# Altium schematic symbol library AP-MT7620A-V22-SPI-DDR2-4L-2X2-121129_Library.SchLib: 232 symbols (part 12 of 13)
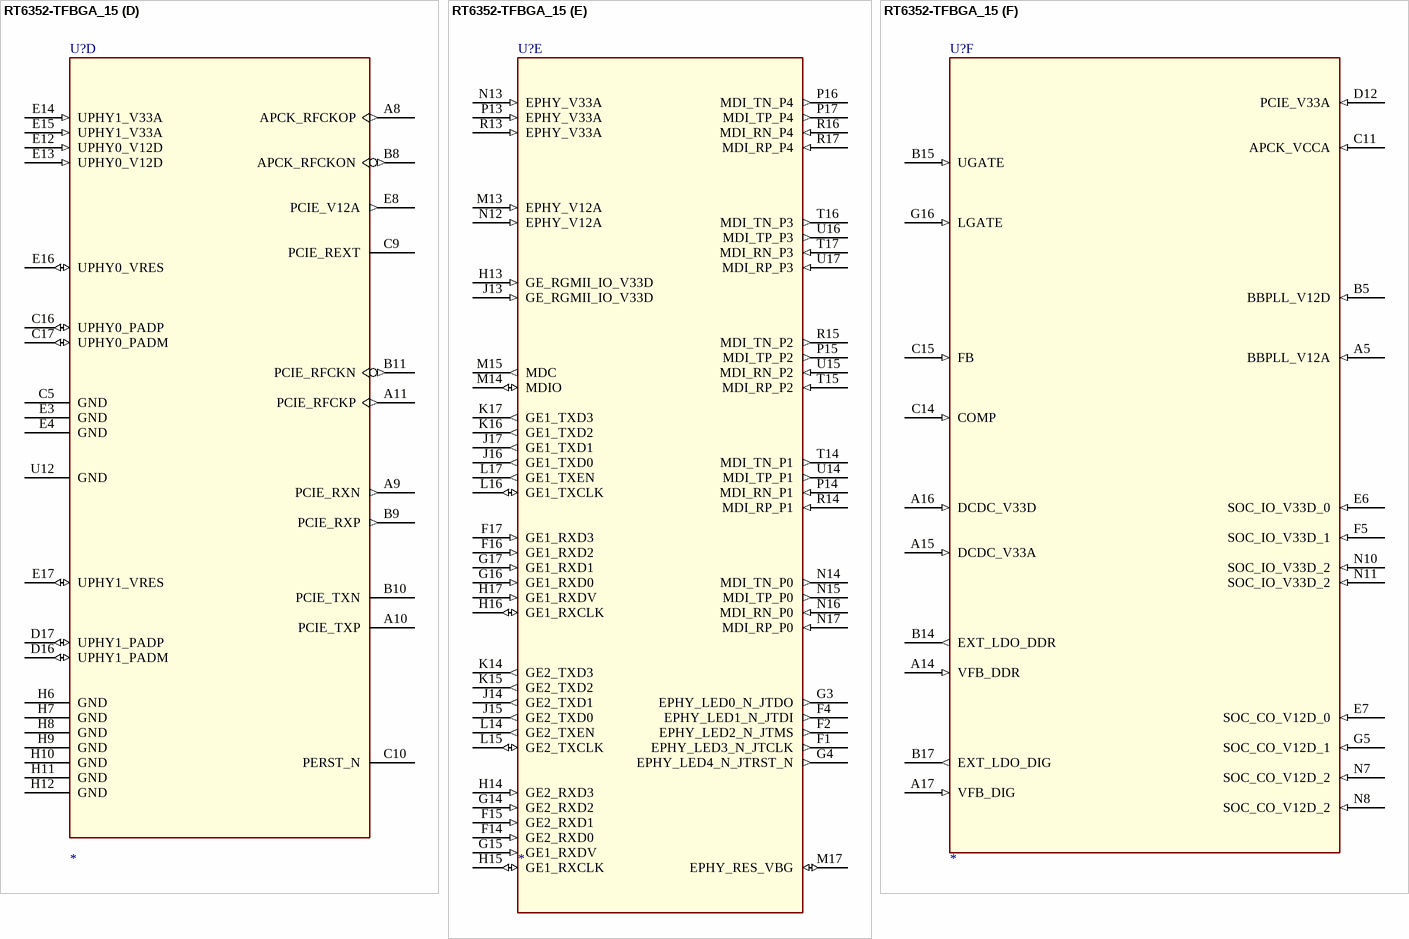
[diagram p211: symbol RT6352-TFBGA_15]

## RT6352-TFBGA_15
designator U?
footprint RT6352/BGA289/P0.65/12X12
part A pins: A1 RF0_PA2_V33P (in), A2 RF0_OUTP (out), A3 PLL_VC_CAP (out), A4 XTAL_XO (out), A6 ANT_TRN (out), B1 RF0_PA2_V33N (in), B2 RF0_OUTN (out), B3 PLL_VX_LDO, B4 XTAL_XI (out), B6 ANT_TRNB (out), C1 RF0_PA1_V33A (in), C2 RF1_VX_LDO, C3 RF0_VX_LDO, C4 XTAL_V12A (out), C6 PA_PE_G0 (out), D1 RF1_PA2_V33P (in), D2 RF1_PA2_V33N (in), D3 RF1_PA1_V33A (in), D4 BG_EXTR (out), D5 BG_V33A, D6 PA_PE_G1 (out), E1 RF1_OUTP (out), E2 RF1_OUTN (out), F3 WLED_N (out)
part B pins: F6 GND (power), F7 GND (power), F8 GND (power), F9 GND (power), F10 GND (power), F11 GND (power), F12 GND (power), G1 MD14 / MD15 (io), G2 MD9 / MD14 (io), G6 GND (power), G7 GND (power), G8 GND (power), G9 GND (power), G10 GND (power), G11 GND (power), G12 GND (power), H1 MD12 / MD13 (io), H2 MD11 / MD12 (io), H3 MRAS_N / MA5 (io), H4 MODT / MA4 (io), H5 DDR_IO_V18D/DDR_IO_V25D (in), J1 MD10 / MD11 (io), J2 MD13 / MD10 (io), J3 MCAS_N / MA7 (io), J4 MCS_N / MA6 (io), J5 DDR_IO_V18D/DDR_IO_V25D (in), K1 MD8 / MD9 (io), K2 MD15 / MD8 (io), K3 MA0 / MA8 (io), K4 MA2 / MA9 (io), K5 DDR_IOC_V12D (in), L1 MDQS1 (in), L2 MDQM1 (io), L3 MA6 / MA12 (io), L4 MA4 / MA11 (io), L5 DDR_IOC_V12D (in), M1 MCK_N (io), M2 MCK_P (io), M3 MA8 / MCKE (io), M5 MA11 / MODT (io), N1 MD5 / MD0 (io), N2 MD2 / MD1 (io), N3 MA9 / MA3 (io), N4 DDR_IO_VREF (in), N5 DDR_IO_V18D/DDR_IO_V25D (in), N6 DDR_IO_V18D/DDR_IO_V25D (in), P1 MD0 / MD2 (io), P2 MD7 / MD3 (io), P3 MA12 / MA2 (io), P4 MA7 / MA1 (io), P5 DDR_IO_VREF (in), R1 MD6 /MD4 (io), R2 MD1 / MD5 (io), R3 MA5 / MA0 (io), R4 MA3 / MA10 (io), T1 MD4 / MD6 (io), T2 MD3 / MD7 (io), T3 MA1 / MBA1 (io), T4 MBA0 / MCS_N (io), T5 MWE_N / MCAS_N (io), U1 MDQS0 (io), U2 MDQM0 (io), U3 MA10 / MBA0 (io), U4 MBA1 / MRAS_N (io), U5 MCKE / MWE_N (io)
part C pins: A7 SPI_CS0 (out), B7 SPI_CS1 (out), B17 PORST_N (in), C7 WDT_RST_N (out), C8 SPI_HOLD (out), D7 GPIO0, D8 SPI_WP (out), D9 SPI_MISO (in), D10 SPI_MOSI (out), D11 SPI_CLK (out), J6 GND (power), J7 GND (power), J8 GND (power), J9 GND (power), J10 GND (power), J11 GND (power), J12 GND (power), K6 GND (power), K7 GND (power), K8 GND (power), K9 GND (power), K10 GND (power), K11 GND (power), K12 GND (power), L6 GND (power), L7 GND (power), L8 GND (power), L9 GND (power), L10 GND (power), L11 GND (power), L12 GND (power), M6 GND (power), M7 GND (power), M8 GND (power), M9 GND (power), M10 GND (power), M11 GND (power), M12 GND (power), P6 TXD2, P7 RTS_N (out), P8 ND_D3/SD_D3 (out), P9 ND_D2/SD_D2 (out), P10 ND_D1/SD_D1 (out), P11 DSR_N (io), P12 RXD (io), R6 RXD2 (in), R7 ND_D5/bt_aux (out), R8 ND_CS_N (out), R9 ND_WP/SD_WP (out), R10 ND_D0/SD_D0 (out), R11 DCD_N (io), R12 RIN (io), T6 I2C_SD (out), T7 ND_D6/bt_wact (out), T8 ND_CLE/SD_card_detect, T9 ND_WE_N (out), T10 ND_ALE/SD_CMD (out), T11 TXD (out), T12 CTS_N (io), U6 I2C_SCLK (io), U7 ND_D7/bt_ant (out), U8 ND_D4/bt_stat (out), U9 ND_RE_N (out), U10 ND_RB_N/SD_CLK (out), U11 DTR_N (out)
part D pins: A8 APCK_RFCKOP (out), A9 PCIE_RXN (out), A10 PCIE_TXP, A11 PCIE_RFCKP (out), B8 APCK_RFCKON (out), B9 PCIE_RXP (out), B10 PCIE_TXN, B11 PCIE_RFCKN (out), C5 GND, C9 PCIE_REXT, C10 PERST_N, C16 UPHY0_PADP (io), C17 UPHY0_PADM (io), D16 UPHY1_PADM (io), D17 UPHY1_PADP (io), E3 GND, E4 GND, E8 PCIE_V12A (out), E12 UPHY0_V12D (in), E13 UPHY0_V12D (in), E14 UPHY1_V33A (in), E15 UPHY1_V33A (in), E16 UPHY0_VRES (io), E17 UPHY1_VRES (io), H6 GND (power), H7 GND (power), H8 GND (power), H9 GND (power), H10 GND (power), H11 GND (power), H12 GND (power), U12 GND
part E pins: F1 EPHY_LED3_N_JTCLK (out), F2 EPHY_LED2_N_JTMS (out), F4 EPHY_LED1_N_JTDI (out), F14 GE2_RXD0 (in), F15 GE2_RXD1 (in), F16 GE1_RXD2 (in), F17 GE1_RXD3 (in), G3 EPHY_LED0_N_JTDO (out), G4 EPHY_LED4_N_JTRST_N (out), G14 GE2_RXD2 (in), G15 GE1_RXDV (in), G16 GE1_RXD0 (in), G17 GE1_RXD1 (in), H13 GE_RGMII_IO_V33D (in), H14 GE2_RXD3 (in), H15 GE1_RXCLK (io), H16 GE1_RXCLK (io), H17 GE1_RXDV (in), J13 GE_RGMII_IO_V33D (in), J14 GE2_TXD1 (out), J15 GE2_TXD0 (out), J16 GE1_TXD0 (out), J17 GE1_TXD1 (out), K14 GE2_TXD3 (out), K15 GE2_TXD2 (out), K16 GE1_TXD2 (out), K17 GE1_TXD3 (out), L14 GE2_TXEN (out), L15 GE2_TXCLK (io), L16 GE1_TXCLK (io), L17 GE1_TXEN (out), M13 EPHY_V12A (in), M14 MDIO (io), M15 MDC (out), M17 EPHY_RES_VBG (io), N12 EPHY_V12A (in), N13 EPHY_V33A (in), N14 MDI_TN_P0 (out), N15 MDI_TP_P0 (out), N16 MDI_RN_P0 (in), N17 MDI_RP_P0 (in), P13 EPHY_V33A (in), P14 MDI_RN_P1 (in), P15 MDI_TP_P2 (out), P16 MDI_TN_P4 (out), P17 MDI_TP_P4 (out), R13 EPHY_V33A (in), R14 MDI_RP_P1 (in), R15 MDI_TN_P2 (out), R16 MDI_RN_P4 (in), R17 MDI_RP_P4 (in), T14 MDI_TN_P1 (out), T15 MDI_RP_P2 (in), T16 MDI_TN_P3 (out), T17 MDI_RN_P3 (in), U14 MDI_TP_P1 (out), U15 MDI_RN_P2 (in), U16 MDI_TP_P3 (out), U17 MDI_RP_P3 (in)
part F pins: A5 BBPLL_V12A (in), A14 VFB_DDR (in), A15 DCDC_V33A (in), A16 DCDC_V33D (in), A17 VFB_DIG (in), B5 BBPLL_V12D (in), B14 EXT_LDO_DDR (out), B15 UGATE (in), B17 EXT_LDO_DIG (out), C11 APCK_VCCA (in), C14 COMP (in), C15 FB (in), D12 PCIE_V33A (in), E6 SOC_IO_V33D_0 (in), E7 SOC_CO_V12D_0 (in), F5 SOC_IO_V33D_1 (in), G5 SOC_CO_V12D_1 (in), G16 LGATE (in), N7 SOC_CO_V12D_2 (in), N8 SOC_CO_V12D_2 (in), N10 SOC_IO_V33D_2 (in), N11 SOC_IO_V33D_2 (in)

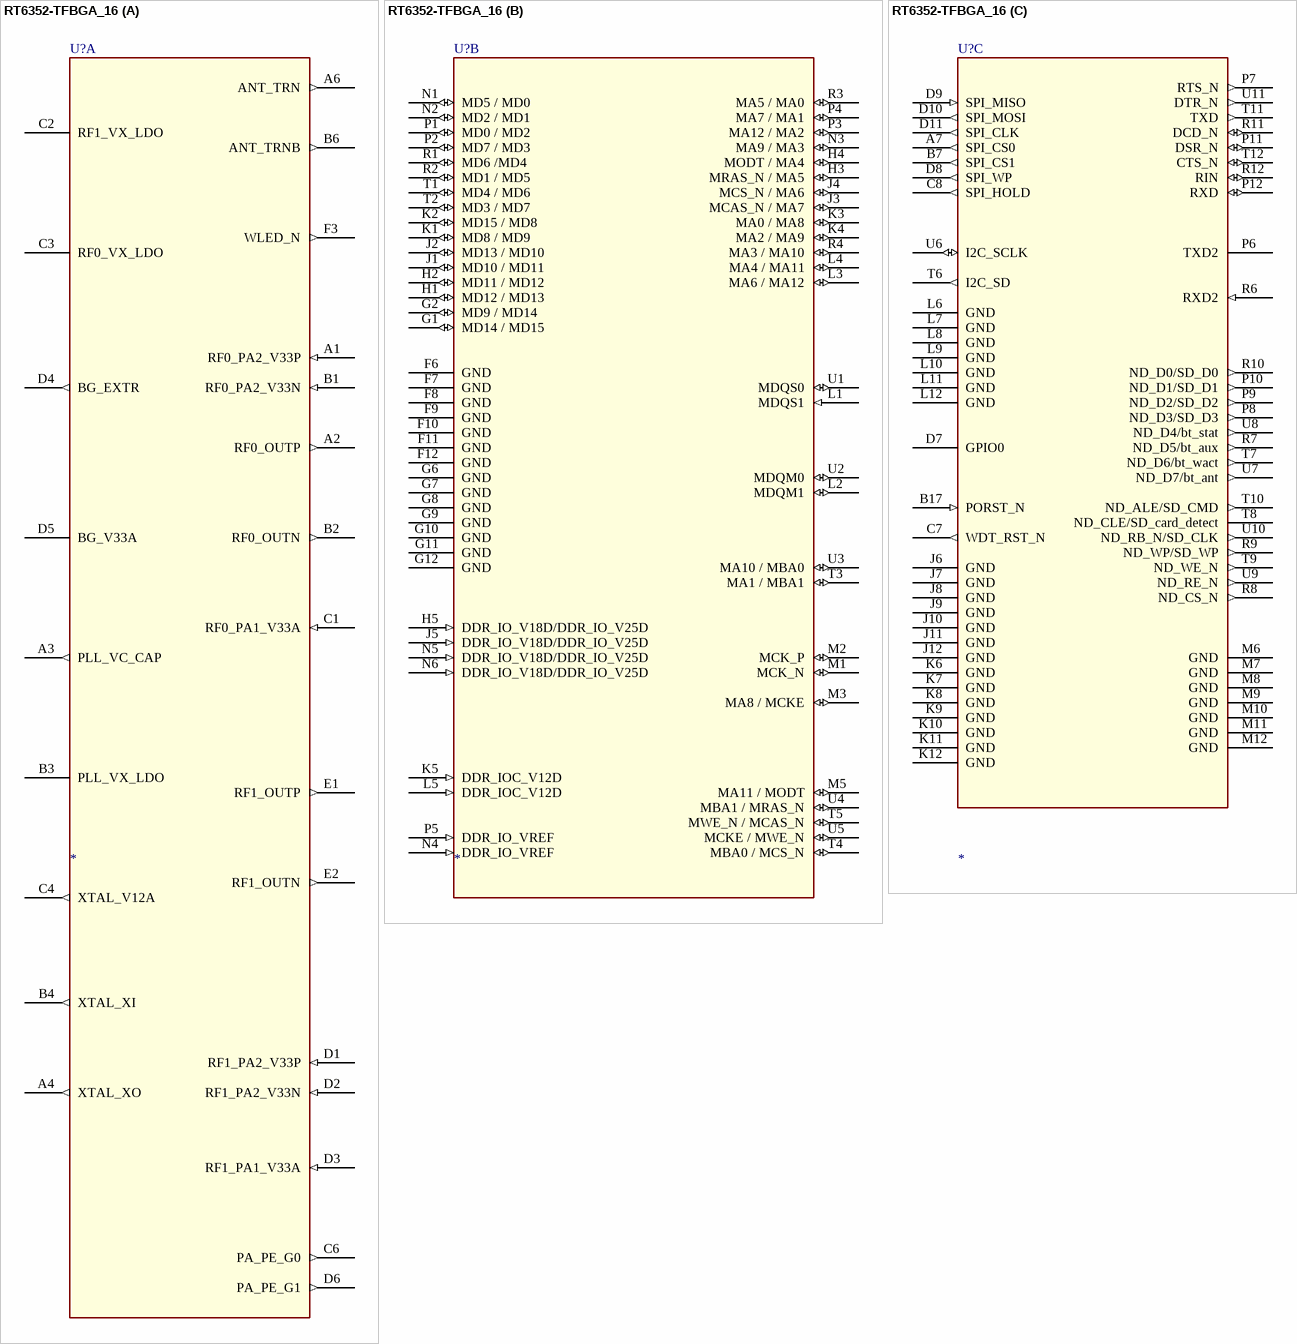
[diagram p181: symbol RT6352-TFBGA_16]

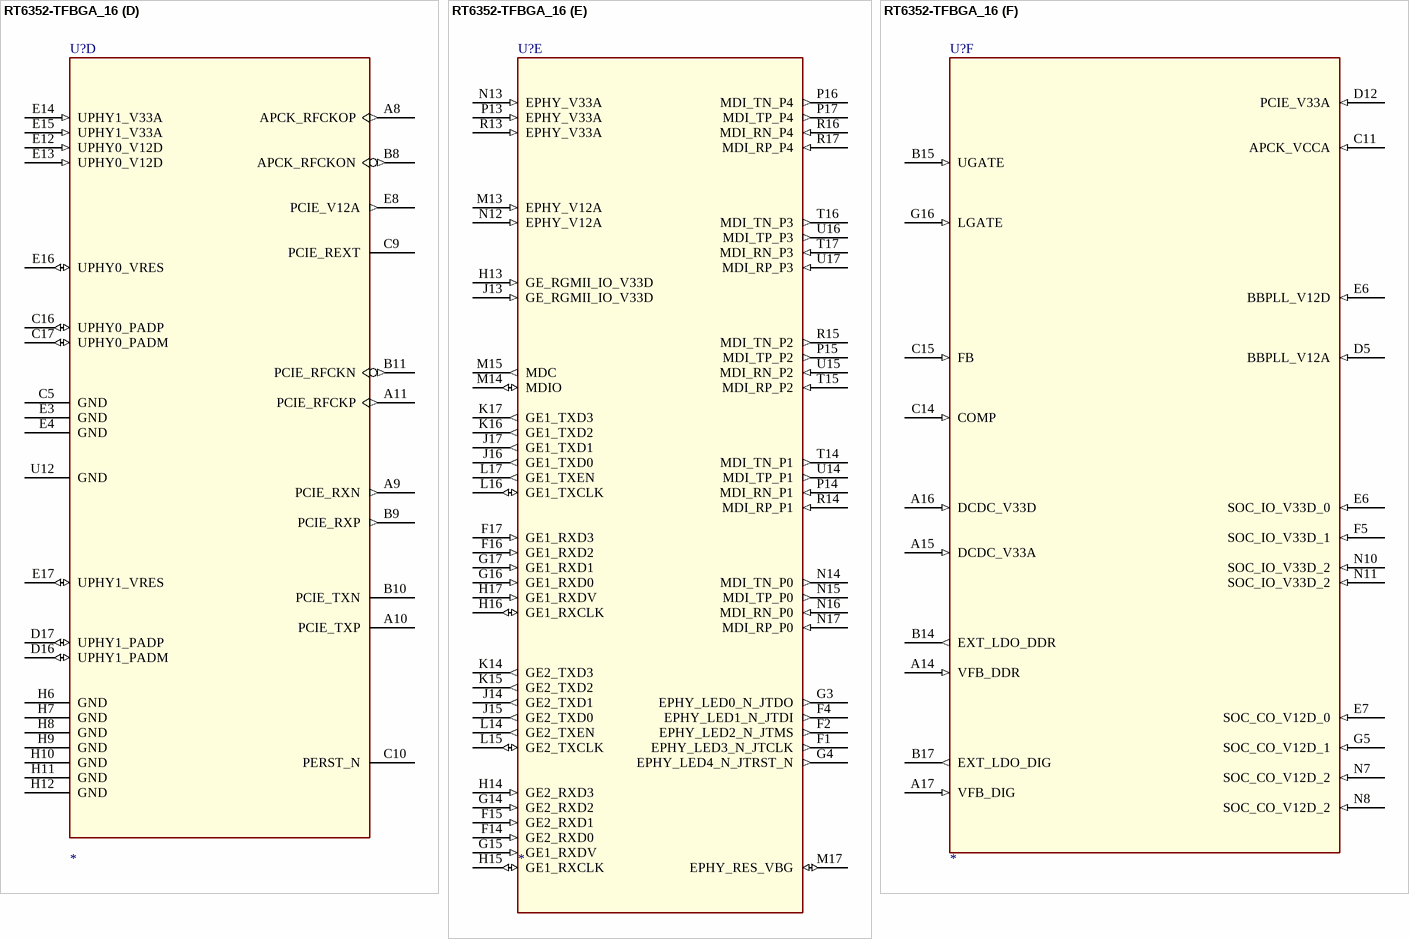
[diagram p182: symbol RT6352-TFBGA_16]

## RT6352-TFBGA_16
designator U?
footprint RT6352/BGA289/P0.65/12X12
part A pins: A1 RF0_PA2_V33P (in), A2 RF0_OUTP (out), A3 PLL_VC_CAP (out), A4 XTAL_XO (out), A6 ANT_TRN (out), B1 RF0_PA2_V33N (in), B2 RF0_OUTN (out), B3 PLL_VX_LDO, B4 XTAL_XI (out), B6 ANT_TRNB (out), C1 RF0_PA1_V33A (in), C2 RF1_VX_LDO, C3 RF0_VX_LDO, C4 XTAL_V12A (out), C6 PA_PE_G0 (out), D1 RF1_PA2_V33P (in), D2 RF1_PA2_V33N (in), D3 RF1_PA1_V33A (in), D4 BG_EXTR (out), D5 BG_V33A, D6 PA_PE_G1 (out), E1 RF1_OUTP (out), E2 RF1_OUTN (out), F3 WLED_N (out)
part B pins: F6 GND (power), F7 GND (power), F8 GND (power), F9 GND (power), F10 GND (power), F11 GND (power), F12 GND (power), G1 MD14 / MD15 (io), G2 MD9 / MD14 (io), G6 GND (power), G7 GND (power), G8 GND (power), G9 GND (power), G10 GND (power), G11 GND (power), G12 GND (power), H1 MD12 / MD13 (io), H2 MD11 / MD12 (io), H3 MRAS_N / MA5 (io), H4 MODT / MA4 (io), H5 DDR_IO_V18D/DDR_IO_V25D (in), J1 MD10 / MD11 (io), J2 MD13 / MD10 (io), J3 MCAS_N / MA7 (io), J4 MCS_N / MA6 (io), J5 DDR_IO_V18D/DDR_IO_V25D (in), K1 MD8 / MD9 (io), K2 MD15 / MD8 (io), K3 MA0 / MA8 (io), K4 MA2 / MA9 (io), K5 DDR_IOC_V12D (in), L1 MDQS1 (in), L2 MDQM1 (io), L3 MA6 / MA12 (io), L4 MA4 / MA11 (io), L5 DDR_IOC_V12D (in), M1 MCK_N (io), M2 MCK_P (io), M3 MA8 / MCKE (io), M5 MA11 / MODT (io), N1 MD5 / MD0 (io), N2 MD2 / MD1 (io), N3 MA9 / MA3 (io), N4 DDR_IO_VREF (in), N5 DDR_IO_V18D/DDR_IO_V25D (in), N6 DDR_IO_V18D/DDR_IO_V25D (in), P1 MD0 / MD2 (io), P2 MD7 / MD3 (io), P3 MA12 / MA2 (io), P4 MA7 / MA1 (io), P5 DDR_IO_VREF (in), R1 MD6 /MD4 (io), R2 MD1 / MD5 (io), R3 MA5 / MA0 (io), R4 MA3 / MA10 (io), T1 MD4 / MD6 (io), T2 MD3 / MD7 (io), T3 MA1 / MBA1 (io), T4 MBA0 / MCS_N (io), T5 MWE_N / MCAS_N (io), U1 MDQS0 (io), U2 MDQM0 (io), U3 MA10 / MBA0 (io), U4 MBA1 / MRAS_N (io), U5 MCKE / MWE_N (io)
part C pins: A7 SPI_CS0 (out), B7 SPI_CS1 (out), B17 PORST_N (in), C7 WDT_RST_N (out), C8 SPI_HOLD (out), D7 GPIO0, D8 SPI_WP (out), D9 SPI_MISO (in), D10 SPI_MOSI (out), D11 SPI_CLK (out), J6 GND (power), J7 GND (power), J8 GND (power), J9 GND (power), J10 GND (power), J11 GND (power), J12 GND (power), K6 GND (power), K7 GND (power), K8 GND (power), K9 GND (power), K10 GND (power), K11 GND (power), K12 GND (power), L6 GND (power), L7 GND (power), L8 GND (power), L9 GND (power), L10 GND (power), L11 GND (power), L12 GND (power), M6 GND (power), M7 GND (power), M8 GND (power), M9 GND (power), M10 GND (power), M11 GND (power), M12 GND (power), P6 TXD2, P7 RTS_N (out), P8 ND_D3/SD_D3 (out), P9 ND_D2/SD_D2 (out), P10 ND_D1/SD_D1 (out), P11 DSR_N (io), P12 RXD (io), R6 RXD2 (in), R7 ND_D5/bt_aux (out), R8 ND_CS_N (out), R9 ND_WP/SD_WP (out), R10 ND_D0/SD_D0 (out), R11 DCD_N (io), R12 RIN (io), T6 I2C_SD (out), T7 ND_D6/bt_wact (out), T8 ND_CLE/SD_card_detect, T9 ND_WE_N (out), T10 ND_ALE/SD_CMD (out), T11 TXD (out), T12 CTS_N (io), U6 I2C_SCLK (io), U7 ND_D7/bt_ant (out), U8 ND_D4/bt_stat (out), U9 ND_RE_N (out), U10 ND_RB_N/SD_CLK (out), U11 DTR_N (out)
part D pins: A8 APCK_RFCKOP (out), A9 PCIE_RXN (out), A10 PCIE_TXP, A11 PCIE_RFCKP (out), B8 APCK_RFCKON (out), B9 PCIE_RXP (out), B10 PCIE_TXN, B11 PCIE_RFCKN (out), C5 GND, C9 PCIE_REXT, C10 PERST_N, C16 UPHY0_PADP (io), C17 UPHY0_PADM (io), D16 UPHY1_PADM (io), D17 UPHY1_PADP (io), E3 GND, E4 GND, E8 PCIE_V12A (out), E12 UPHY0_V12D (in), E13 UPHY0_V12D (in), E14 UPHY1_V33A (in), E15 UPHY1_V33A (in), E16 UPHY0_VRES (io), E17 UPHY1_VRES (io), H6 GND (power), H7 GND (power), H8 GND (power), H9 GND (power), H10 GND (power), H11 GND (power), H12 GND (power), U12 GND
part E pins: F1 EPHY_LED3_N_JTCLK (out), F2 EPHY_LED2_N_JTMS (out), F4 EPHY_LED1_N_JTDI (out), F14 GE2_RXD0 (in), F15 GE2_RXD1 (in), F16 GE1_RXD2 (in), F17 GE1_RXD3 (in), G3 EPHY_LED0_N_JTDO (out), G4 EPHY_LED4_N_JTRST_N (out), G14 GE2_RXD2 (in), G15 GE1_RXDV (in), G16 GE1_RXD0 (in), G17 GE1_RXD1 (in), H13 GE_RGMII_IO_V33D (in), H14 GE2_RXD3 (in), H15 GE1_RXCLK (io), H16 GE1_RXCLK (io), H17 GE1_RXDV (in), J13 GE_RGMII_IO_V33D (in), J14 GE2_TXD1 (out), J15 GE2_TXD0 (out), J16 GE1_TXD0 (out), J17 GE1_TXD1 (out), K14 GE2_TXD3 (out), K15 GE2_TXD2 (out), K16 GE1_TXD2 (out), K17 GE1_TXD3 (out), L14 GE2_TXEN (out), L15 GE2_TXCLK (io), L16 GE1_TXCLK (io), L17 GE1_TXEN (out), M13 EPHY_V12A (in), M14 MDIO (io), M15 MDC (out), M17 EPHY_RES_VBG (io), N12 EPHY_V12A (in), N13 EPHY_V33A (in), N14 MDI_TN_P0 (out), N15 MDI_TP_P0 (out), N16 MDI_RN_P0 (in), N17 MDI_RP_P0 (in), P13 EPHY_V33A (in), P14 MDI_RN_P1 (in), P15 MDI_TP_P2 (out), P16 MDI_TN_P4 (out), P17 MDI_TP_P4 (out), R13 EPHY_V33A (in), R14 MDI_RP_P1 (in), R15 MDI_TN_P2 (out), R16 MDI_RN_P4 (in), R17 MDI_RP_P4 (in), T14 MDI_TN_P1 (out), T15 MDI_RP_P2 (in), T16 MDI_TN_P3 (out), T17 MDI_RN_P3 (in), U14 MDI_TP_P1 (out), U15 MDI_RN_P2 (in), U16 MDI_TP_P3 (out), U17 MDI_RP_P3 (in)
part F pins: A14 VFB_DDR (in), A15 DCDC_V33A (in), A16 DCDC_V33D (in), A17 VFB_DIG (in), B14 EXT_LDO_DDR (out), B15 UGATE (in), B17 EXT_LDO_DIG (out), C11 APCK_VCCA (in), C14 COMP (in), C15 FB (in), D5 BBPLL_V12A (in), D12 PCIE_V33A (in), E6 SOC_IO_V33D_0 (in), E6 BBPLL_V12D (in), E7 SOC_CO_V12D_0 (in), F5 SOC_IO_V33D_1 (in), G5 SOC_CO_V12D_1 (in), G16 LGATE (in), N7 SOC_CO_V12D_2 (in), N8 SOC_CO_V12D_2 (in), N10 SOC_IO_V33D_2 (in), N11 SOC_IO_V33D_2 (in)

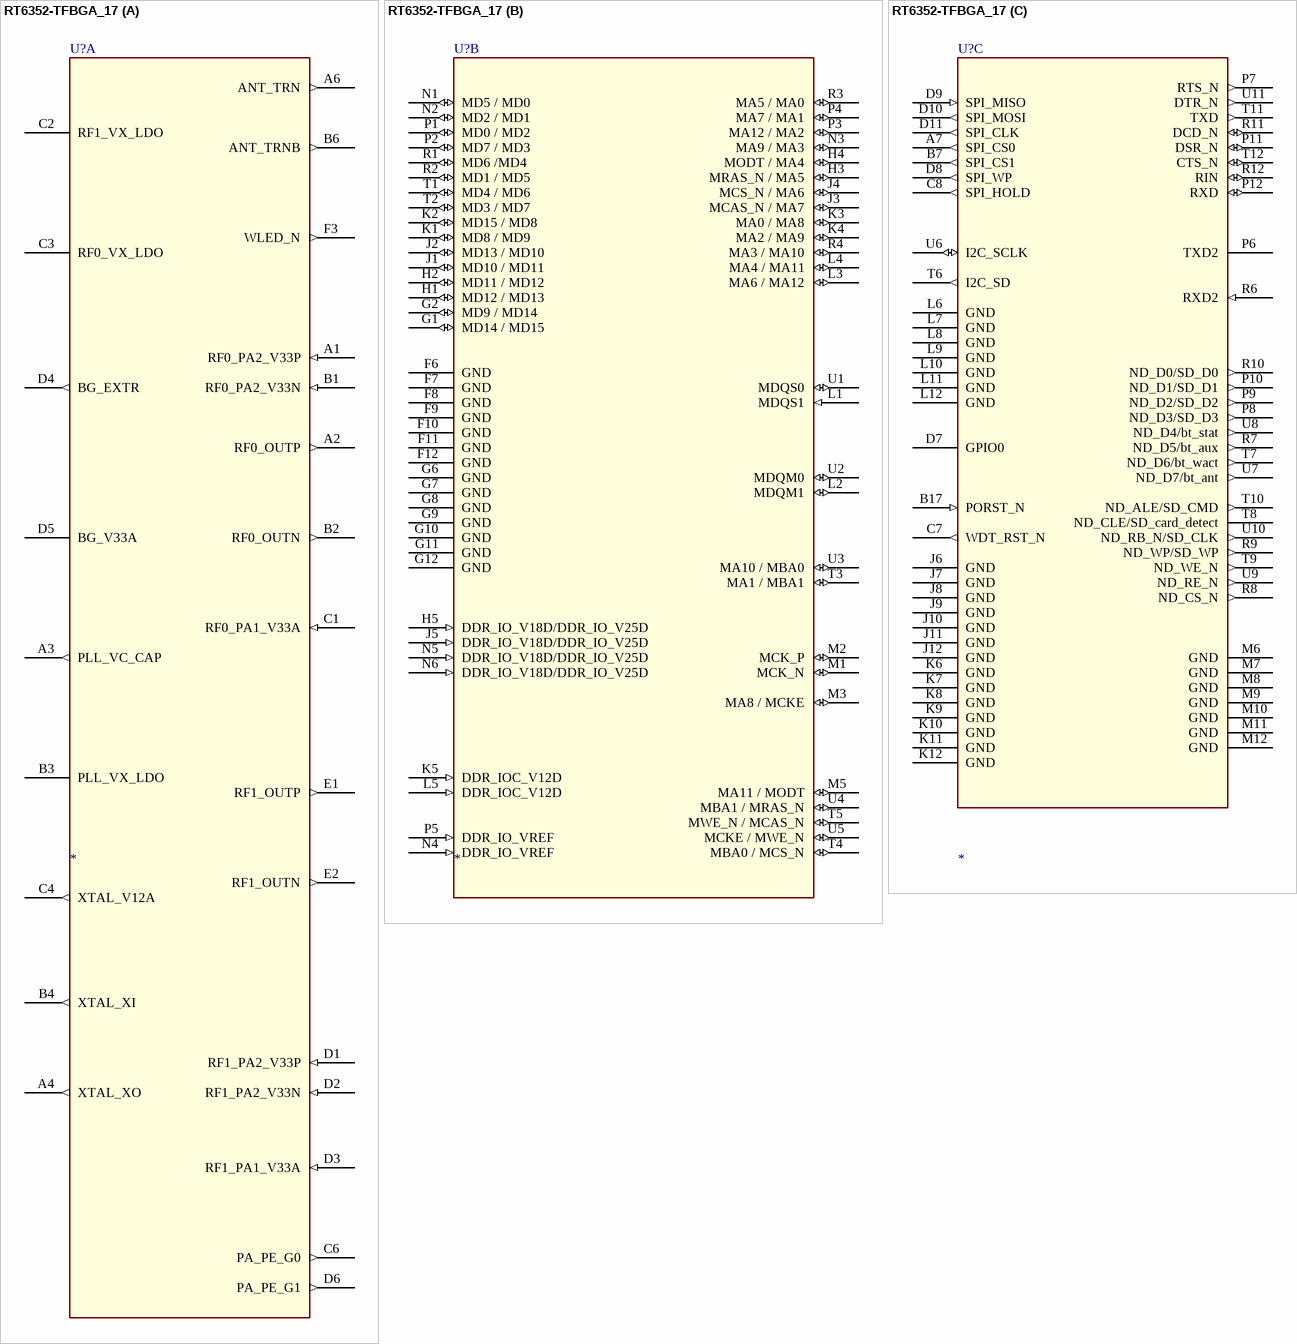
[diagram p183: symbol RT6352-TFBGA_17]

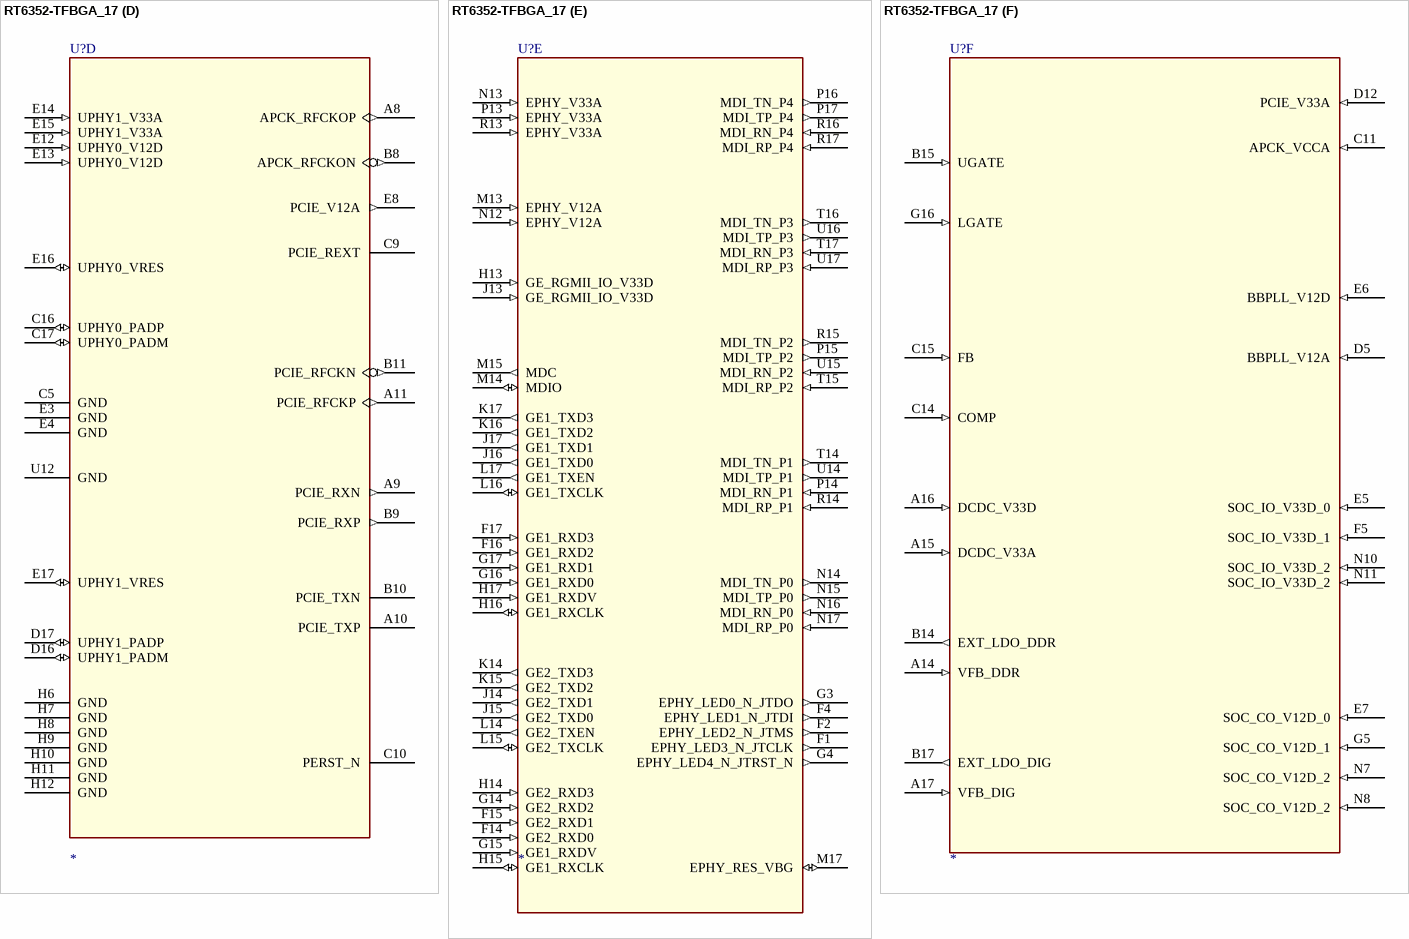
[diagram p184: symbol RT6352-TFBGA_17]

## RT6352-TFBGA_17
designator U?
footprint RT6352/BGA289/P0.65/12X12
part A pins: A1 RF0_PA2_V33P (in), A2 RF0_OUTP (out), A3 PLL_VC_CAP (out), A4 XTAL_XO (out), A6 ANT_TRN (out), B1 RF0_PA2_V33N (in), B2 RF0_OUTN (out), B3 PLL_VX_LDO, B4 XTAL_XI (out), B6 ANT_TRNB (out), C1 RF0_PA1_V33A (in), C2 RF1_VX_LDO, C3 RF0_VX_LDO, C4 XTAL_V12A (out), C6 PA_PE_G0 (out), D1 RF1_PA2_V33P (in), D2 RF1_PA2_V33N (in), D3 RF1_PA1_V33A (in), D4 BG_EXTR (out), D5 BG_V33A, D6 PA_PE_G1 (out), E1 RF1_OUTP (out), E2 RF1_OUTN (out), F3 WLED_N (out)
part B pins: F6 GND (power), F7 GND (power), F8 GND (power), F9 GND (power), F10 GND (power), F11 GND (power), F12 GND (power), G1 MD14 / MD15 (io), G2 MD9 / MD14 (io), G6 GND (power), G7 GND (power), G8 GND (power), G9 GND (power), G10 GND (power), G11 GND (power), G12 GND (power), H1 MD12 / MD13 (io), H2 MD11 / MD12 (io), H3 MRAS_N / MA5 (io), H4 MODT / MA4 (io), H5 DDR_IO_V18D/DDR_IO_V25D (in), J1 MD10 / MD11 (io), J2 MD13 / MD10 (io), J3 MCAS_N / MA7 (io), J4 MCS_N / MA6 (io), J5 DDR_IO_V18D/DDR_IO_V25D (in), K1 MD8 / MD9 (io), K2 MD15 / MD8 (io), K3 MA0 / MA8 (io), K4 MA2 / MA9 (io), K5 DDR_IOC_V12D (in), L1 MDQS1 (in), L2 MDQM1 (io), L3 MA6 / MA12 (io), L4 MA4 / MA11 (io), L5 DDR_IOC_V12D (in), M1 MCK_N (io), M2 MCK_P (io), M3 MA8 / MCKE (io), M5 MA11 / MODT (io), N1 MD5 / MD0 (io), N2 MD2 / MD1 (io), N3 MA9 / MA3 (io), N4 DDR_IO_VREF (in), N5 DDR_IO_V18D/DDR_IO_V25D (in), N6 DDR_IO_V18D/DDR_IO_V25D (in), P1 MD0 / MD2 (io), P2 MD7 / MD3 (io), P3 MA12 / MA2 (io), P4 MA7 / MA1 (io), P5 DDR_IO_VREF (in), R1 MD6 /MD4 (io), R2 MD1 / MD5 (io), R3 MA5 / MA0 (io), R4 MA3 / MA10 (io), T1 MD4 / MD6 (io), T2 MD3 / MD7 (io), T3 MA1 / MBA1 (io), T4 MBA0 / MCS_N (io), T5 MWE_N / MCAS_N (io), U1 MDQS0 (io), U2 MDQM0 (io), U3 MA10 / MBA0 (io), U4 MBA1 / MRAS_N (io), U5 MCKE / MWE_N (io)
part C pins: A7 SPI_CS0 (out), B7 SPI_CS1 (out), B17 PORST_N (in), C7 WDT_RST_N (out), C8 SPI_HOLD (out), D7 GPIO0, D8 SPI_WP (out), D9 SPI_MISO (in), D10 SPI_MOSI (out), D11 SPI_CLK (out), J6 GND (power), J7 GND (power), J8 GND (power), J9 GND (power), J10 GND (power), J11 GND (power), J12 GND (power), K6 GND (power), K7 GND (power), K8 GND (power), K9 GND (power), K10 GND (power), K11 GND (power), K12 GND (power), L6 GND (power), L7 GND (power), L8 GND (power), L9 GND (power), L10 GND (power), L11 GND (power), L12 GND (power), M6 GND (power), M7 GND (power), M8 GND (power), M9 GND (power), M10 GND (power), M11 GND (power), M12 GND (power), P6 TXD2, P7 RTS_N (out), P8 ND_D3/SD_D3 (out), P9 ND_D2/SD_D2 (out), P10 ND_D1/SD_D1 (out), P11 DSR_N (io), P12 RXD (io), R6 RXD2 (in), R7 ND_D5/bt_aux (out), R8 ND_CS_N (out), R9 ND_WP/SD_WP (out), R10 ND_D0/SD_D0 (out), R11 DCD_N (io), R12 RIN (io), T6 I2C_SD (out), T7 ND_D6/bt_wact (out), T8 ND_CLE/SD_card_detect, T9 ND_WE_N (out), T10 ND_ALE/SD_CMD (out), T11 TXD (out), T12 CTS_N (io), U6 I2C_SCLK (io), U7 ND_D7/bt_ant (out), U8 ND_D4/bt_stat (out), U9 ND_RE_N (out), U10 ND_RB_N/SD_CLK (out), U11 DTR_N (out)
part D pins: A8 APCK_RFCKOP (out), A9 PCIE_RXN (out), A10 PCIE_TXP, A11 PCIE_RFCKP (out), B8 APCK_RFCKON (out), B9 PCIE_RXP (out), B10 PCIE_TXN, B11 PCIE_RFCKN (out), C5 GND, C9 PCIE_REXT, C10 PERST_N, C16 UPHY0_PADP (io), C17 UPHY0_PADM (io), D16 UPHY1_PADM (io), D17 UPHY1_PADP (io), E3 GND, E4 GND, E8 PCIE_V12A (out), E12 UPHY0_V12D (in), E13 UPHY0_V12D (in), E14 UPHY1_V33A (in), E15 UPHY1_V33A (in), E16 UPHY0_VRES (io), E17 UPHY1_VRES (io), H6 GND (power), H7 GND (power), H8 GND (power), H9 GND (power), H10 GND (power), H11 GND (power), H12 GND (power), U12 GND
part E pins: F1 EPHY_LED3_N_JTCLK (out), F2 EPHY_LED2_N_JTMS (out), F4 EPHY_LED1_N_JTDI (out), F14 GE2_RXD0 (in), F15 GE2_RXD1 (in), F16 GE1_RXD2 (in), F17 GE1_RXD3 (in), G3 EPHY_LED0_N_JTDO (out), G4 EPHY_LED4_N_JTRST_N (out), G14 GE2_RXD2 (in), G15 GE1_RXDV (in), G16 GE1_RXD0 (in), G17 GE1_RXD1 (in), H13 GE_RGMII_IO_V33D (in), H14 GE2_RXD3 (in), H15 GE1_RXCLK (io), H16 GE1_RXCLK (io), H17 GE1_RXDV (in), J13 GE_RGMII_IO_V33D (in), J14 GE2_TXD1 (out), J15 GE2_TXD0 (out), J16 GE1_TXD0 (out), J17 GE1_TXD1 (out), K14 GE2_TXD3 (out), K15 GE2_TXD2 (out), K16 GE1_TXD2 (out), K17 GE1_TXD3 (out), L14 GE2_TXEN (out), L15 GE2_TXCLK (io), L16 GE1_TXCLK (io), L17 GE1_TXEN (out), M13 EPHY_V12A (in), M14 MDIO (io), M15 MDC (out), M17 EPHY_RES_VBG (io), N12 EPHY_V12A (in), N13 EPHY_V33A (in), N14 MDI_TN_P0 (out), N15 MDI_TP_P0 (out), N16 MDI_RN_P0 (in), N17 MDI_RP_P0 (in), P13 EPHY_V33A (in), P14 MDI_RN_P1 (in), P15 MDI_TP_P2 (out), P16 MDI_TN_P4 (out), P17 MDI_TP_P4 (out), R13 EPHY_V33A (in), R14 MDI_RP_P1 (in), R15 MDI_TN_P2 (out), R16 MDI_RN_P4 (in), R17 MDI_RP_P4 (in), T14 MDI_TN_P1 (out), T15 MDI_RP_P2 (in), T16 MDI_TN_P3 (out), T17 MDI_RN_P3 (in), U14 MDI_TP_P1 (out), U15 MDI_RN_P2 (in), U16 MDI_TP_P3 (out), U17 MDI_RP_P3 (in)
part F pins: A14 VFB_DDR (in), A15 DCDC_V33A (in), A16 DCDC_V33D (in), A17 VFB_DIG (in), B14 EXT_LDO_DDR (out), B15 UGATE (in), B17 EXT_LDO_DIG (out), C11 APCK_VCCA (in), C14 COMP (in), C15 FB (in), D5 BBPLL_V12A (in), D12 PCIE_V33A (in), E5 SOC_IO_V33D_0 (in), E6 BBPLL_V12D (in), E7 SOC_CO_V12D_0 (in), F5 SOC_IO_V33D_1 (in), G5 SOC_CO_V12D_1 (in), G16 LGATE (in), N7 SOC_CO_V12D_2 (in), N8 SOC_CO_V12D_2 (in), N10 SOC_IO_V33D_2 (in), N11 SOC_IO_V33D_2 (in)

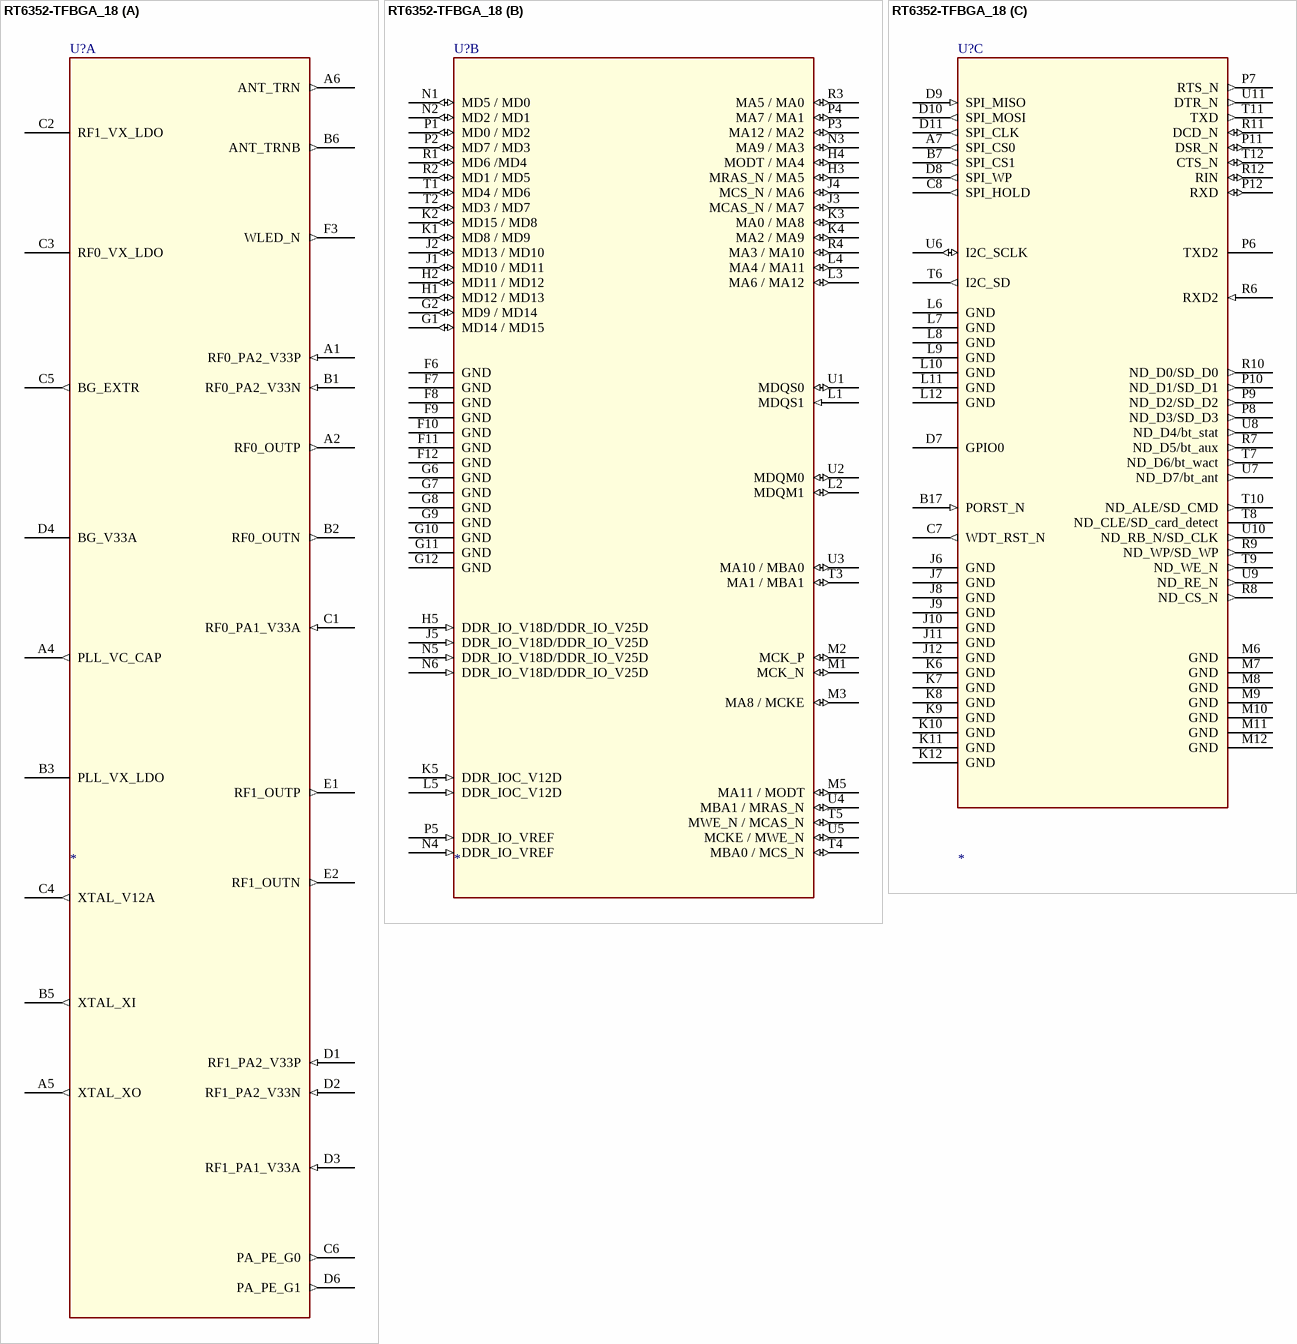
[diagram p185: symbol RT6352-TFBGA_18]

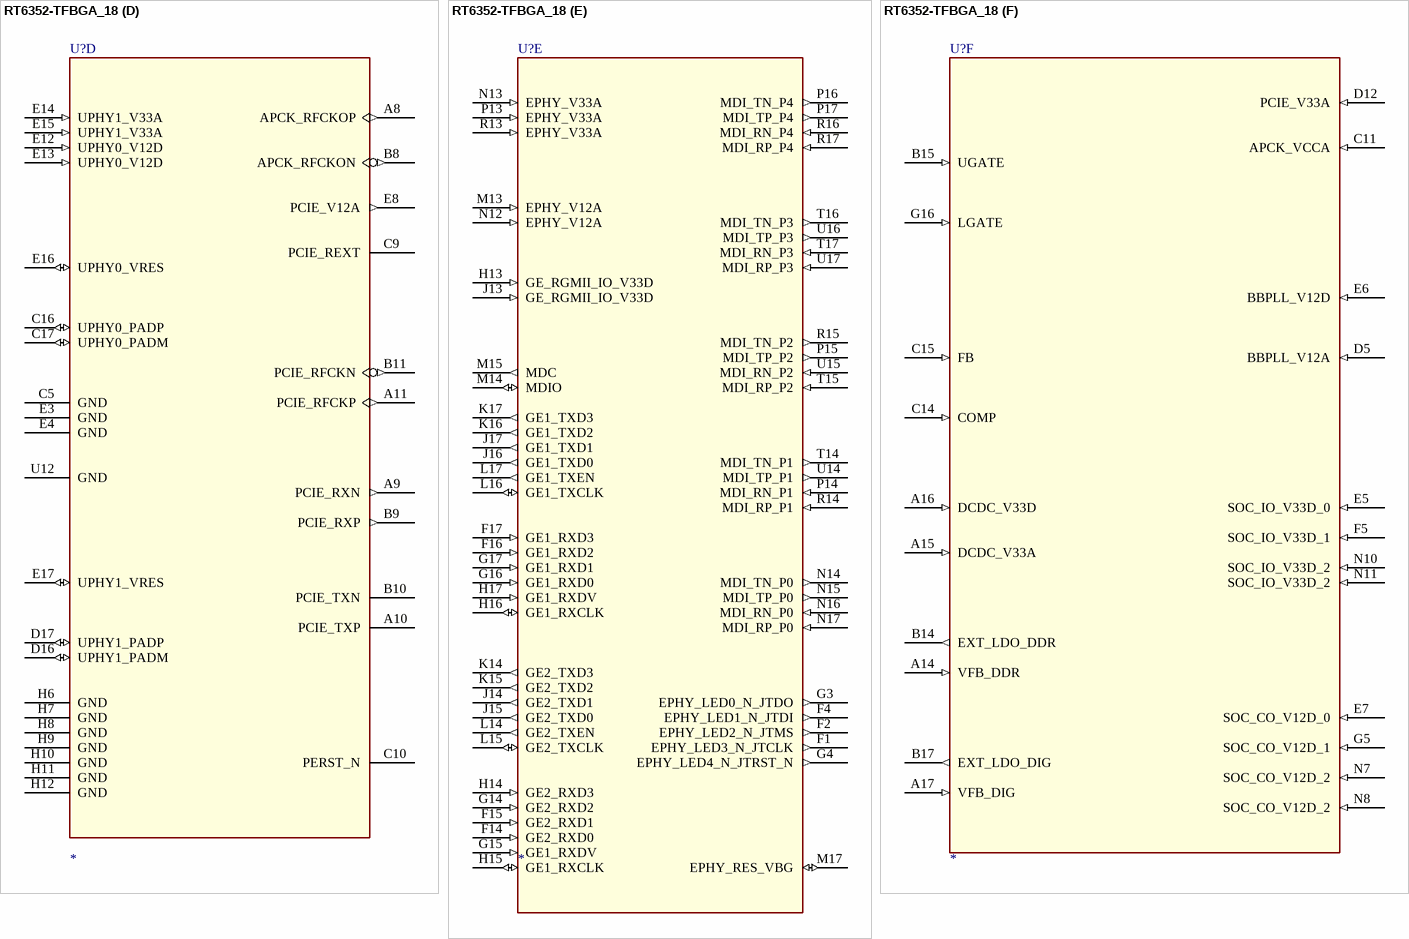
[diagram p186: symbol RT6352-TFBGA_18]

## RT6352-TFBGA_18
designator U?
footprint RT6352/BGA289/P0.65/12X12
part A pins: A1 RF0_PA2_V33P (in), A2 RF0_OUTP (out), A4 PLL_VC_CAP (out), A5 XTAL_XO (out), A6 ANT_TRN (out), B1 RF0_PA2_V33N (in), B2 RF0_OUTN (out), B3 PLL_VX_LDO, B5 XTAL_XI (out), B6 ANT_TRNB (out), C1 RF0_PA1_V33A (in), C2 RF1_VX_LDO, C3 RF0_VX_LDO, C4 XTAL_V12A (out), C5 BG_EXTR (out), C6 PA_PE_G0 (out), D1 RF1_PA2_V33P (in), D2 RF1_PA2_V33N (in), D3 RF1_PA1_V33A (in), D4 BG_V33A, D6 PA_PE_G1 (out), E1 RF1_OUTP (out), E2 RF1_OUTN (out), F3 WLED_N (out)
part B pins: F6 GND (power), F7 GND (power), F8 GND (power), F9 GND (power), F10 GND (power), F11 GND (power), F12 GND (power), G1 MD14 / MD15 (io), G2 MD9 / MD14 (io), G6 GND (power), G7 GND (power), G8 GND (power), G9 GND (power), G10 GND (power), G11 GND (power), G12 GND (power), H1 MD12 / MD13 (io), H2 MD11 / MD12 (io), H3 MRAS_N / MA5 (io), H4 MODT / MA4 (io), H5 DDR_IO_V18D/DDR_IO_V25D (in), J1 MD10 / MD11 (io), J2 MD13 / MD10 (io), J3 MCAS_N / MA7 (io), J4 MCS_N / MA6 (io), J5 DDR_IO_V18D/DDR_IO_V25D (in), K1 MD8 / MD9 (io), K2 MD15 / MD8 (io), K3 MA0 / MA8 (io), K4 MA2 / MA9 (io), K5 DDR_IOC_V12D (in), L1 MDQS1 (in), L2 MDQM1 (io), L3 MA6 / MA12 (io), L4 MA4 / MA11 (io), L5 DDR_IOC_V12D (in), M1 MCK_N (io), M2 MCK_P (io), M3 MA8 / MCKE (io), M5 MA11 / MODT (io), N1 MD5 / MD0 (io), N2 MD2 / MD1 (io), N3 MA9 / MA3 (io), N4 DDR_IO_VREF (in), N5 DDR_IO_V18D/DDR_IO_V25D (in), N6 DDR_IO_V18D/DDR_IO_V25D (in), P1 MD0 / MD2 (io), P2 MD7 / MD3 (io), P3 MA12 / MA2 (io), P4 MA7 / MA1 (io), P5 DDR_IO_VREF (in), R1 MD6 /MD4 (io), R2 MD1 / MD5 (io), R3 MA5 / MA0 (io), R4 MA3 / MA10 (io), T1 MD4 / MD6 (io), T2 MD3 / MD7 (io), T3 MA1 / MBA1 (io), T4 MBA0 / MCS_N (io), T5 MWE_N / MCAS_N (io), U1 MDQS0 (io), U2 MDQM0 (io), U3 MA10 / MBA0 (io), U4 MBA1 / MRAS_N (io), U5 MCKE / MWE_N (io)
part C pins: A7 SPI_CS0 (out), B7 SPI_CS1 (out), B17 PORST_N (in), C7 WDT_RST_N (out), C8 SPI_HOLD (out), D7 GPIO0, D8 SPI_WP (out), D9 SPI_MISO (in), D10 SPI_MOSI (out), D11 SPI_CLK (out), J6 GND (power), J7 GND (power), J8 GND (power), J9 GND (power), J10 GND (power), J11 GND (power), J12 GND (power), K6 GND (power), K7 GND (power), K8 GND (power), K9 GND (power), K10 GND (power), K11 GND (power), K12 GND (power), L6 GND (power), L7 GND (power), L8 GND (power), L9 GND (power), L10 GND (power), L11 GND (power), L12 GND (power), M6 GND (power), M7 GND (power), M8 GND (power), M9 GND (power), M10 GND (power), M11 GND (power), M12 GND (power), P6 TXD2, P7 RTS_N (out), P8 ND_D3/SD_D3 (out), P9 ND_D2/SD_D2 (out), P10 ND_D1/SD_D1 (out), P11 DSR_N (io), P12 RXD (io), R6 RXD2 (in), R7 ND_D5/bt_aux (out), R8 ND_CS_N (out), R9 ND_WP/SD_WP (out), R10 ND_D0/SD_D0 (out), R11 DCD_N (io), R12 RIN (io), T6 I2C_SD (out), T7 ND_D6/bt_wact (out), T8 ND_CLE/SD_card_detect, T9 ND_WE_N (out), T10 ND_ALE/SD_CMD (out), T11 TXD (out), T12 CTS_N (io), U6 I2C_SCLK (io), U7 ND_D7/bt_ant (out), U8 ND_D4/bt_stat (out), U9 ND_RE_N (out), U10 ND_RB_N/SD_CLK (out), U11 DTR_N (out)
part D pins: A8 APCK_RFCKOP (out), A9 PCIE_RXN (out), A10 PCIE_TXP, A11 PCIE_RFCKP (out), B8 APCK_RFCKON (out), B9 PCIE_RXP (out), B10 PCIE_TXN, B11 PCIE_RFCKN (out), C5 GND, C9 PCIE_REXT, C10 PERST_N, C16 UPHY0_PADP (io), C17 UPHY0_PADM (io), D16 UPHY1_PADM (io), D17 UPHY1_PADP (io), E3 GND, E4 GND, E8 PCIE_V12A (out), E12 UPHY0_V12D (in), E13 UPHY0_V12D (in), E14 UPHY1_V33A (in), E15 UPHY1_V33A (in), E16 UPHY0_VRES (io), E17 UPHY1_VRES (io), H6 GND (power), H7 GND (power), H8 GND (power), H9 GND (power), H10 GND (power), H11 GND (power), H12 GND (power), U12 GND
part E pins: F1 EPHY_LED3_N_JTCLK (out), F2 EPHY_LED2_N_JTMS (out), F4 EPHY_LED1_N_JTDI (out), F14 GE2_RXD0 (in), F15 GE2_RXD1 (in), F16 GE1_RXD2 (in), F17 GE1_RXD3 (in), G3 EPHY_LED0_N_JTDO (out), G4 EPHY_LED4_N_JTRST_N (out), G14 GE2_RXD2 (in), G15 GE1_RXDV (in), G16 GE1_RXD0 (in), G17 GE1_RXD1 (in), H13 GE_RGMII_IO_V33D (in), H14 GE2_RXD3 (in), H15 GE1_RXCLK (io), H16 GE1_RXCLK (io), H17 GE1_RXDV (in), J13 GE_RGMII_IO_V33D (in), J14 GE2_TXD1 (out), J15 GE2_TXD0 (out), J16 GE1_TXD0 (out), J17 GE1_TXD1 (out), K14 GE2_TXD3 (out), K15 GE2_TXD2 (out), K16 GE1_TXD2 (out), K17 GE1_TXD3 (out), L14 GE2_TXEN (out), L15 GE2_TXCLK (io), L16 GE1_TXCLK (io), L17 GE1_TXEN (out), M13 EPHY_V12A (in), M14 MDIO (io), M15 MDC (out), M17 EPHY_RES_VBG (io), N12 EPHY_V12A (in), N13 EPHY_V33A (in), N14 MDI_TN_P0 (out), N15 MDI_TP_P0 (out), N16 MDI_RN_P0 (in), N17 MDI_RP_P0 (in), P13 EPHY_V33A (in), P14 MDI_RN_P1 (in), P15 MDI_TP_P2 (out), P16 MDI_TN_P4 (out), P17 MDI_TP_P4 (out), R13 EPHY_V33A (in), R14 MDI_RP_P1 (in), R15 MDI_TN_P2 (out), R16 MDI_RN_P4 (in), R17 MDI_RP_P4 (in), T14 MDI_TN_P1 (out), T15 MDI_RP_P2 (in), T16 MDI_TN_P3 (out), T17 MDI_RN_P3 (in), U14 MDI_TP_P1 (out), U15 MDI_RN_P2 (in), U16 MDI_TP_P3 (out), U17 MDI_RP_P3 (in)
part F pins: A14 VFB_DDR (in), A15 DCDC_V33A (in), A16 DCDC_V33D (in), A17 VFB_DIG (in), B14 EXT_LDO_DDR (out), B15 UGATE (in), B17 EXT_LDO_DIG (out), C11 APCK_VCCA (in), C14 COMP (in), C15 FB (in), D5 BBPLL_V12A (in), D12 PCIE_V33A (in), E5 SOC_IO_V33D_0 (in), E6 BBPLL_V12D (in), E7 SOC_CO_V12D_0 (in), F5 SOC_IO_V33D_1 (in), G5 SOC_CO_V12D_1 (in), G16 LGATE (in), N7 SOC_CO_V12D_2 (in), N8 SOC_CO_V12D_2 (in), N10 SOC_IO_V33D_2 (in), N11 SOC_IO_V33D_2 (in)

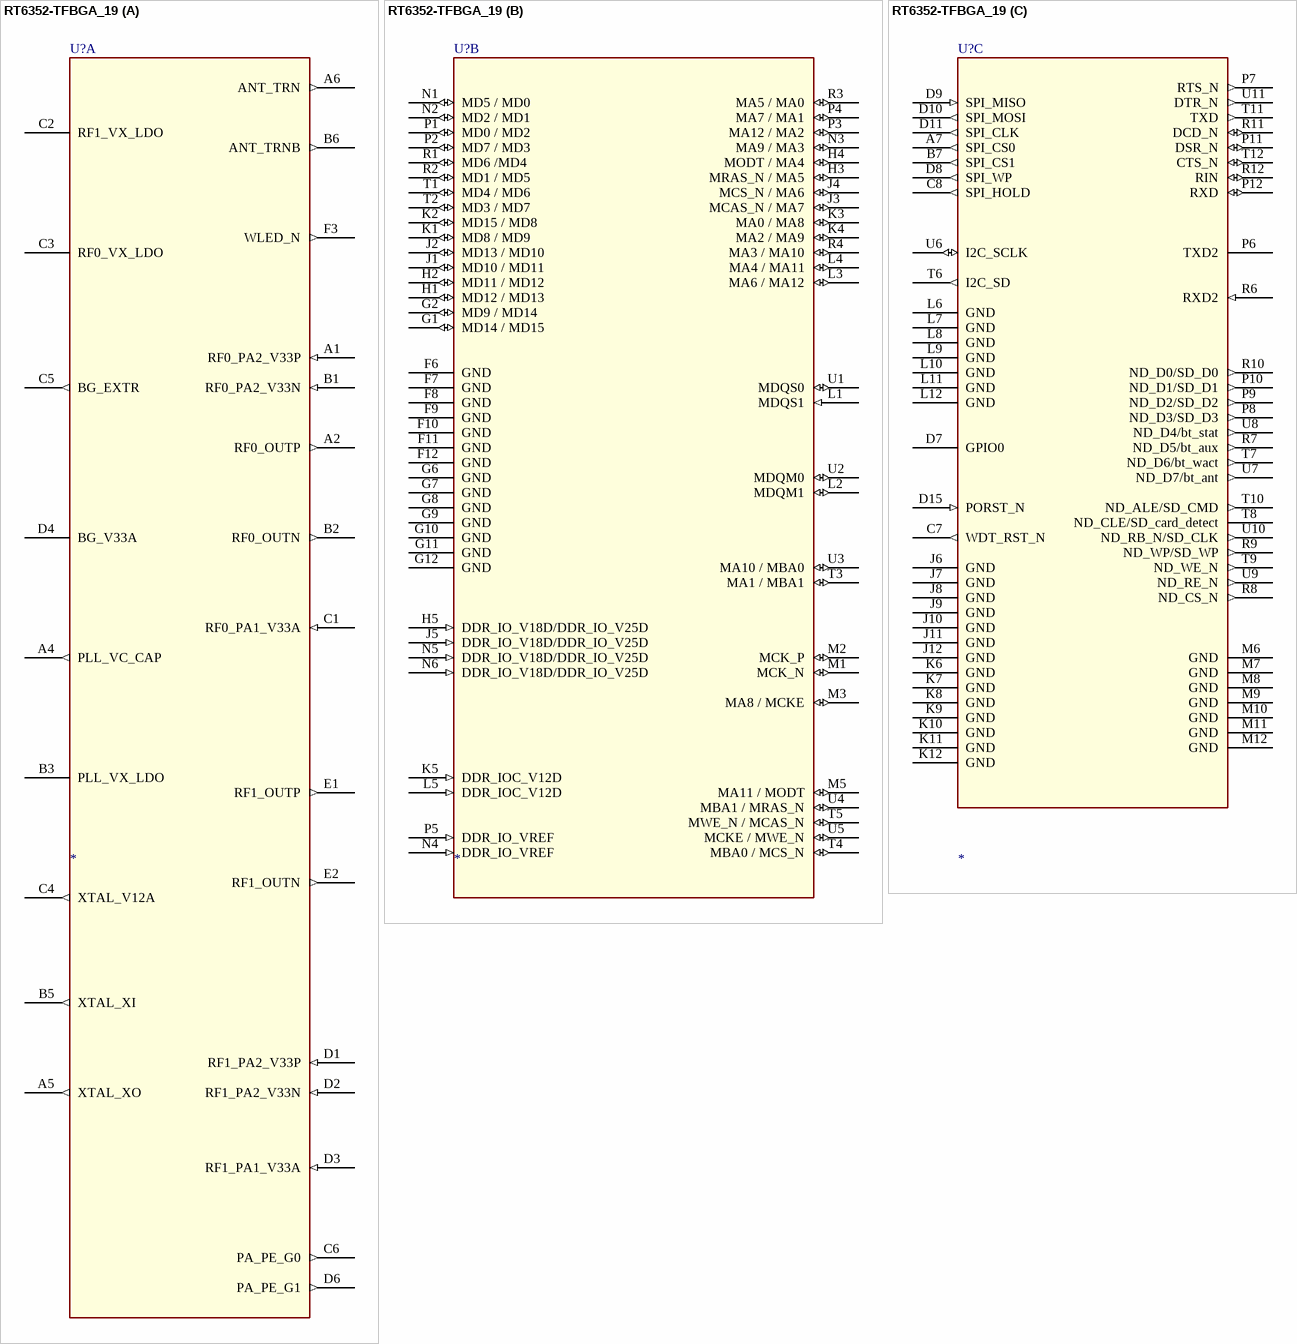
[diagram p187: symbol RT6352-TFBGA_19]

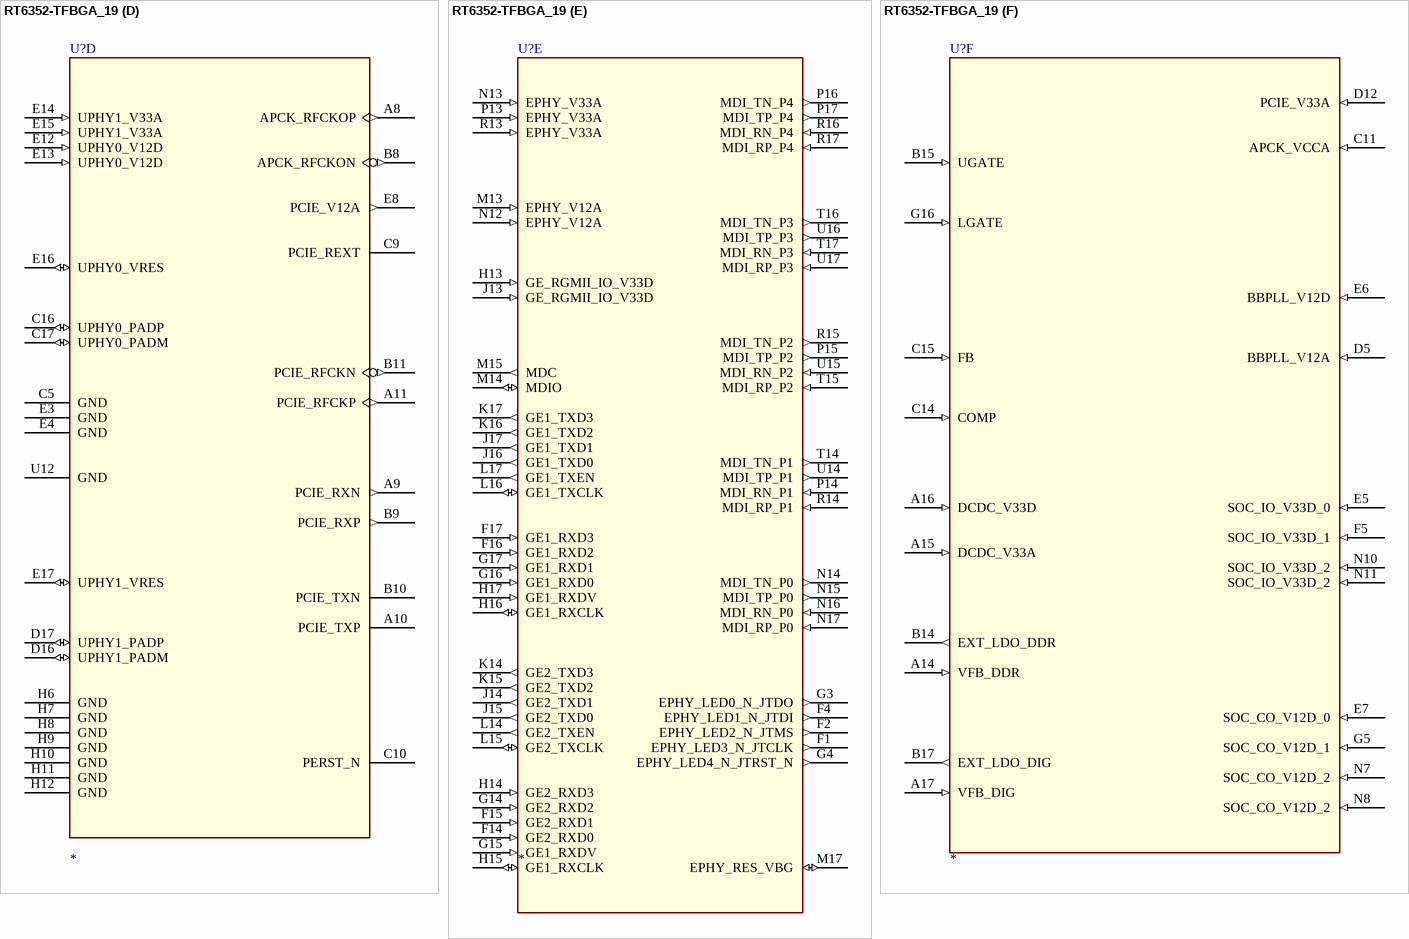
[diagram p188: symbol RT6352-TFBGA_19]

## RT6352-TFBGA_19
designator U?
footprint RT6352/BGA289/P0.65/12X12
part A pins: A1 RF0_PA2_V33P (in), A2 RF0_OUTP (out), A4 PLL_VC_CAP (out), A5 XTAL_XO (out), A6 ANT_TRN (out), B1 RF0_PA2_V33N (in), B2 RF0_OUTN (out), B3 PLL_VX_LDO, B5 XTAL_XI (out), B6 ANT_TRNB (out), C1 RF0_PA1_V33A (in), C2 RF1_VX_LDO, C3 RF0_VX_LDO, C4 XTAL_V12A (out), C5 BG_EXTR (out), C6 PA_PE_G0 (out), D1 RF1_PA2_V33P (in), D2 RF1_PA2_V33N (in), D3 RF1_PA1_V33A (in), D4 BG_V33A, D6 PA_PE_G1 (out), E1 RF1_OUTP (out), E2 RF1_OUTN (out), F3 WLED_N (out)
part B pins: F6 GND (power), F7 GND (power), F8 GND (power), F9 GND (power), F10 GND (power), F11 GND (power), F12 GND (power), G1 MD14 / MD15 (io), G2 MD9 / MD14 (io), G6 GND (power), G7 GND (power), G8 GND (power), G9 GND (power), G10 GND (power), G11 GND (power), G12 GND (power), H1 MD12 / MD13 (io), H2 MD11 / MD12 (io), H3 MRAS_N / MA5 (io), H4 MODT / MA4 (io), H5 DDR_IO_V18D/DDR_IO_V25D (in), J1 MD10 / MD11 (io), J2 MD13 / MD10 (io), J3 MCAS_N / MA7 (io), J4 MCS_N / MA6 (io), J5 DDR_IO_V18D/DDR_IO_V25D (in), K1 MD8 / MD9 (io), K2 MD15 / MD8 (io), K3 MA0 / MA8 (io), K4 MA2 / MA9 (io), K5 DDR_IOC_V12D (in), L1 MDQS1 (in), L2 MDQM1 (io), L3 MA6 / MA12 (io), L4 MA4 / MA11 (io), L5 DDR_IOC_V12D (in), M1 MCK_N (io), M2 MCK_P (io), M3 MA8 / MCKE (io), M5 MA11 / MODT (io), N1 MD5 / MD0 (io), N2 MD2 / MD1 (io), N3 MA9 / MA3 (io), N4 DDR_IO_VREF (in), N5 DDR_IO_V18D/DDR_IO_V25D (in), N6 DDR_IO_V18D/DDR_IO_V25D (in), P1 MD0 / MD2 (io), P2 MD7 / MD3 (io), P3 MA12 / MA2 (io), P4 MA7 / MA1 (io), P5 DDR_IO_VREF (in), R1 MD6 /MD4 (io), R2 MD1 / MD5 (io), R3 MA5 / MA0 (io), R4 MA3 / MA10 (io), T1 MD4 / MD6 (io), T2 MD3 / MD7 (io), T3 MA1 / MBA1 (io), T4 MBA0 / MCS_N (io), T5 MWE_N / MCAS_N (io), U1 MDQS0 (io), U2 MDQM0 (io), U3 MA10 / MBA0 (io), U4 MBA1 / MRAS_N (io), U5 MCKE / MWE_N (io)
part C pins: A7 SPI_CS0 (out), B7 SPI_CS1 (out), C7 WDT_RST_N (out), C8 SPI_HOLD (out), D7 GPIO0, D8 SPI_WP (out), D9 SPI_MISO (in), D10 SPI_MOSI (out), D11 SPI_CLK (out), D15 PORST_N (in), J6 GND (power), J7 GND (power), J8 GND (power), J9 GND (power), J10 GND (power), J11 GND (power), J12 GND (power), K6 GND (power), K7 GND (power), K8 GND (power), K9 GND (power), K10 GND (power), K11 GND (power), K12 GND (power), L6 GND (power), L7 GND (power), L8 GND (power), L9 GND (power), L10 GND (power), L11 GND (power), L12 GND (power), M6 GND (power), M7 GND (power), M8 GND (power), M9 GND (power), M10 GND (power), M11 GND (power), M12 GND (power), P6 TXD2, P7 RTS_N (out), P8 ND_D3/SD_D3 (out), P9 ND_D2/SD_D2 (out), P10 ND_D1/SD_D1 (out), P11 DSR_N (io), P12 RXD (io), R6 RXD2 (in), R7 ND_D5/bt_aux (out), R8 ND_CS_N (out), R9 ND_WP/SD_WP (out), R10 ND_D0/SD_D0 (out), R11 DCD_N (io), R12 RIN (io), T6 I2C_SD (out), T7 ND_D6/bt_wact (out), T8 ND_CLE/SD_card_detect, T9 ND_WE_N (out), T10 ND_ALE/SD_CMD (out), T11 TXD (out), T12 CTS_N (io), U6 I2C_SCLK (io), U7 ND_D7/bt_ant (out), U8 ND_D4/bt_stat (out), U9 ND_RE_N (out), U10 ND_RB_N/SD_CLK (out), U11 DTR_N (out)
part D pins: A8 APCK_RFCKOP (out), A9 PCIE_RXN (out), A10 PCIE_TXP, A11 PCIE_RFCKP (out), B8 APCK_RFCKON (out), B9 PCIE_RXP (out), B10 PCIE_TXN, B11 PCIE_RFCKN (out), C5 GND, C9 PCIE_REXT, C10 PERST_N, C16 UPHY0_PADP (io), C17 UPHY0_PADM (io), D16 UPHY1_PADM (io), D17 UPHY1_PADP (io), E3 GND, E4 GND, E8 PCIE_V12A (out), E12 UPHY0_V12D (in), E13 UPHY0_V12D (in), E14 UPHY1_V33A (in), E15 UPHY1_V33A (in), E16 UPHY0_VRES (io), E17 UPHY1_VRES (io), H6 GND (power), H7 GND (power), H8 GND (power), H9 GND (power), H10 GND (power), H11 GND (power), H12 GND (power), U12 GND
part E pins: F1 EPHY_LED3_N_JTCLK (out), F2 EPHY_LED2_N_JTMS (out), F4 EPHY_LED1_N_JTDI (out), F14 GE2_RXD0 (in), F15 GE2_RXD1 (in), F16 GE1_RXD2 (in), F17 GE1_RXD3 (in), G3 EPHY_LED0_N_JTDO (out), G4 EPHY_LED4_N_JTRST_N (out), G14 GE2_RXD2 (in), G15 GE1_RXDV (in), G16 GE1_RXD0 (in), G17 GE1_RXD1 (in), H13 GE_RGMII_IO_V33D (in), H14 GE2_RXD3 (in), H15 GE1_RXCLK (io), H16 GE1_RXCLK (io), H17 GE1_RXDV (in), J13 GE_RGMII_IO_V33D (in), J14 GE2_TXD1 (out), J15 GE2_TXD0 (out), J16 GE1_TXD0 (out), J17 GE1_TXD1 (out), K14 GE2_TXD3 (out), K15 GE2_TXD2 (out), K16 GE1_TXD2 (out), K17 GE1_TXD3 (out), L14 GE2_TXEN (out), L15 GE2_TXCLK (io), L16 GE1_TXCLK (io), L17 GE1_TXEN (out), M13 EPHY_V12A (in), M14 MDIO (io), M15 MDC (out), M17 EPHY_RES_VBG (io), N12 EPHY_V12A (in), N13 EPHY_V33A (in), N14 MDI_TN_P0 (out), N15 MDI_TP_P0 (out), N16 MDI_RN_P0 (in), N17 MDI_RP_P0 (in), P13 EPHY_V33A (in), P14 MDI_RN_P1 (in), P15 MDI_TP_P2 (out), P16 MDI_TN_P4 (out), P17 MDI_TP_P4 (out), R13 EPHY_V33A (in), R14 MDI_RP_P1 (in), R15 MDI_TN_P2 (out), R16 MDI_RN_P4 (in), R17 MDI_RP_P4 (in), T14 MDI_TN_P1 (out), T15 MDI_RP_P2 (in), T16 MDI_TN_P3 (out), T17 MDI_RN_P3 (in), U14 MDI_TP_P1 (out), U15 MDI_RN_P2 (in), U16 MDI_TP_P3 (out), U17 MDI_RP_P3 (in)
part F pins: A14 VFB_DDR (in), A15 DCDC_V33A (in), A16 DCDC_V33D (in), A17 VFB_DIG (in), B14 EXT_LDO_DDR (out), B15 UGATE (in), B17 EXT_LDO_DIG (out), C11 APCK_VCCA (in), C14 COMP (in), C15 FB (in), D5 BBPLL_V12A (in), D12 PCIE_V33A (in), E5 SOC_IO_V33D_0 (in), E6 BBPLL_V12D (in), E7 SOC_CO_V12D_0 (in), F5 SOC_IO_V33D_1 (in), G5 SOC_CO_V12D_1 (in), G16 LGATE (in), N7 SOC_CO_V12D_2 (in), N8 SOC_CO_V12D_2 (in), N10 SOC_IO_V33D_2 (in), N11 SOC_IO_V33D_2 (in)

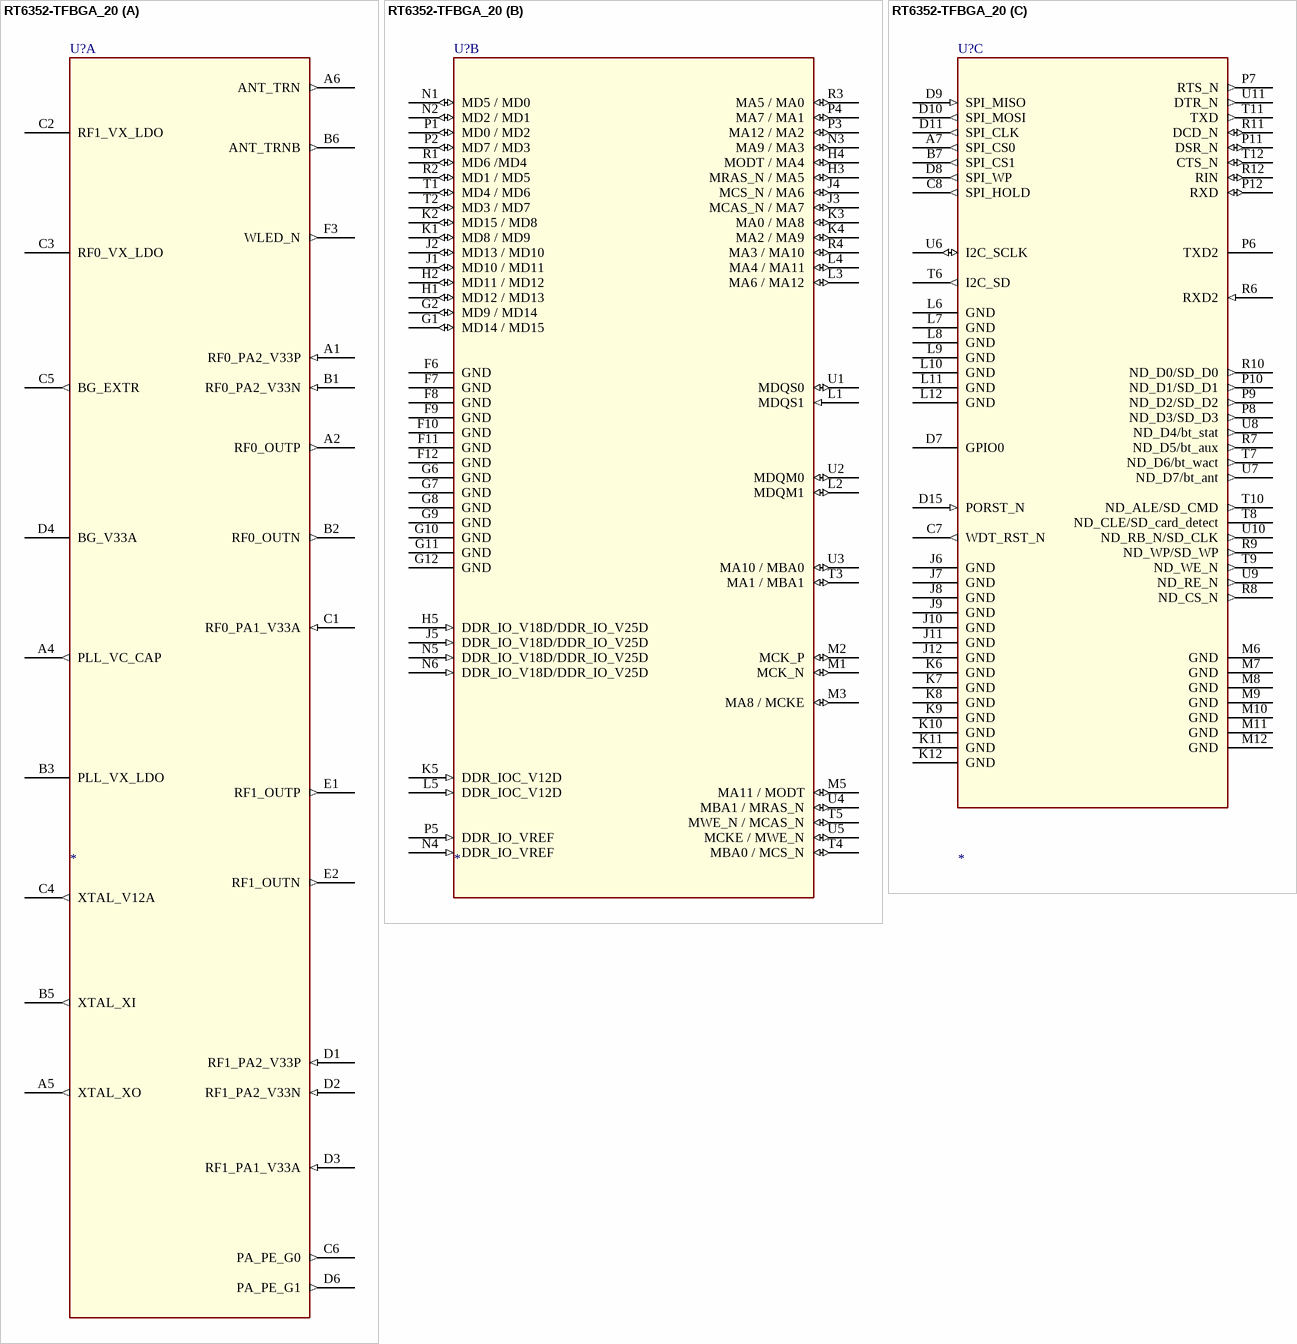
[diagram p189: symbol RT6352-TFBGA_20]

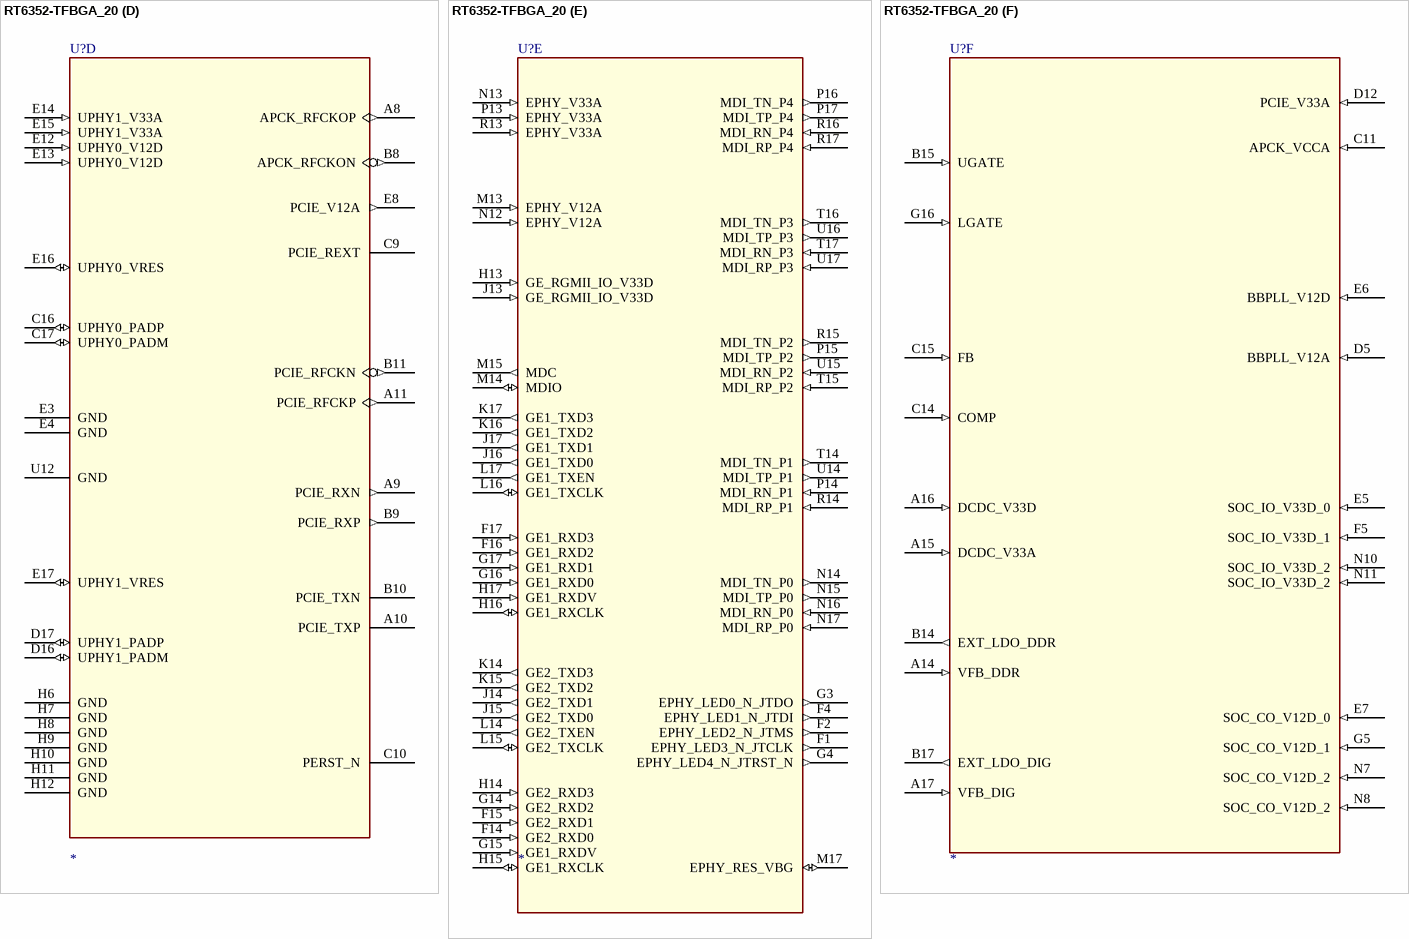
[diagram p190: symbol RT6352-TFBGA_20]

## RT6352-TFBGA_20
designator U?
footprint RT6352/BGA289/P0.65/12X12
part A pins: A1 RF0_PA2_V33P (in), A2 RF0_OUTP (out), A4 PLL_VC_CAP (out), A5 XTAL_XO (out), A6 ANT_TRN (out), B1 RF0_PA2_V33N (in), B2 RF0_OUTN (out), B3 PLL_VX_LDO, B5 XTAL_XI (out), B6 ANT_TRNB (out), C1 RF0_PA1_V33A (in), C2 RF1_VX_LDO, C3 RF0_VX_LDO, C4 XTAL_V12A (out), C5 BG_EXTR (out), C6 PA_PE_G0 (out), D1 RF1_PA2_V33P (in), D2 RF1_PA2_V33N (in), D3 RF1_PA1_V33A (in), D4 BG_V33A, D6 PA_PE_G1 (out), E1 RF1_OUTP (out), E2 RF1_OUTN (out), F3 WLED_N (out)
part B pins: F6 GND (power), F7 GND (power), F8 GND (power), F9 GND (power), F10 GND (power), F11 GND (power), F12 GND (power), G1 MD14 / MD15 (io), G2 MD9 / MD14 (io), G6 GND (power), G7 GND (power), G8 GND (power), G9 GND (power), G10 GND (power), G11 GND (power), G12 GND (power), H1 MD12 / MD13 (io), H2 MD11 / MD12 (io), H3 MRAS_N / MA5 (io), H4 MODT / MA4 (io), H5 DDR_IO_V18D/DDR_IO_V25D (in), J1 MD10 / MD11 (io), J2 MD13 / MD10 (io), J3 MCAS_N / MA7 (io), J4 MCS_N / MA6 (io), J5 DDR_IO_V18D/DDR_IO_V25D (in), K1 MD8 / MD9 (io), K2 MD15 / MD8 (io), K3 MA0 / MA8 (io), K4 MA2 / MA9 (io), K5 DDR_IOC_V12D (in), L1 MDQS1 (in), L2 MDQM1 (io), L3 MA6 / MA12 (io), L4 MA4 / MA11 (io), L5 DDR_IOC_V12D (in), M1 MCK_N (io), M2 MCK_P (io), M3 MA8 / MCKE (io), M5 MA11 / MODT (io), N1 MD5 / MD0 (io), N2 MD2 / MD1 (io), N3 MA9 / MA3 (io), N4 DDR_IO_VREF (in), N5 DDR_IO_V18D/DDR_IO_V25D (in), N6 DDR_IO_V18D/DDR_IO_V25D (in), P1 MD0 / MD2 (io), P2 MD7 / MD3 (io), P3 MA12 / MA2 (io), P4 MA7 / MA1 (io), P5 DDR_IO_VREF (in), R1 MD6 /MD4 (io), R2 MD1 / MD5 (io), R3 MA5 / MA0 (io), R4 MA3 / MA10 (io), T1 MD4 / MD6 (io), T2 MD3 / MD7 (io), T3 MA1 / MBA1 (io), T4 MBA0 / MCS_N (io), T5 MWE_N / MCAS_N (io), U1 MDQS0 (io), U2 MDQM0 (io), U3 MA10 / MBA0 (io), U4 MBA1 / MRAS_N (io), U5 MCKE / MWE_N (io)
part C pins: A7 SPI_CS0 (out), B7 SPI_CS1 (out), C7 WDT_RST_N (out), C8 SPI_HOLD (out), D7 GPIO0, D8 SPI_WP (out), D9 SPI_MISO (in), D10 SPI_MOSI (out), D11 SPI_CLK (out), D15 PORST_N (in), J6 GND (power), J7 GND (power), J8 GND (power), J9 GND (power), J10 GND (power), J11 GND (power), J12 GND (power), K6 GND (power), K7 GND (power), K8 GND (power), K9 GND (power), K10 GND (power), K11 GND (power), K12 GND (power), L6 GND (power), L7 GND (power), L8 GND (power), L9 GND (power), L10 GND (power), L11 GND (power), L12 GND (power), M6 GND (power), M7 GND (power), M8 GND (power), M9 GND (power), M10 GND (power), M11 GND (power), M12 GND (power), P6 TXD2, P7 RTS_N (out), P8 ND_D3/SD_D3 (out), P9 ND_D2/SD_D2 (out), P10 ND_D1/SD_D1 (out), P11 DSR_N (io), P12 RXD (io), R6 RXD2 (in), R7 ND_D5/bt_aux (out), R8 ND_CS_N (out), R9 ND_WP/SD_WP (out), R10 ND_D0/SD_D0 (out), R11 DCD_N (io), R12 RIN (io), T6 I2C_SD (out), T7 ND_D6/bt_wact (out), T8 ND_CLE/SD_card_detect, T9 ND_WE_N (out), T10 ND_ALE/SD_CMD (out), T11 TXD (out), T12 CTS_N (io), U6 I2C_SCLK (io), U7 ND_D7/bt_ant (out), U8 ND_D4/bt_stat (out), U9 ND_RE_N (out), U10 ND_RB_N/SD_CLK (out), U11 DTR_N (out)
part D pins: A8 APCK_RFCKOP (out), A9 PCIE_RXN (out), A10 PCIE_TXP, A11 PCIE_RFCKP (out), B8 APCK_RFCKON (out), B9 PCIE_RXP (out), B10 PCIE_TXN, B11 PCIE_RFCKN (out), C9 PCIE_REXT, C10 PERST_N, C16 UPHY0_PADP (io), C17 UPHY0_PADM (io), D16 UPHY1_PADM (io), D17 UPHY1_PADP (io), E3 GND, E4 GND, E8 PCIE_V12A (out), E12 UPHY0_V12D (in), E13 UPHY0_V12D (in), E14 UPHY1_V33A (in), E15 UPHY1_V33A (in), E16 UPHY0_VRES (io), E17 UPHY1_VRES (io), H6 GND (power), H7 GND (power), H8 GND (power), H9 GND (power), H10 GND (power), H11 GND (power), H12 GND (power), U12 GND
part E pins: F1 EPHY_LED3_N_JTCLK (out), F2 EPHY_LED2_N_JTMS (out), F4 EPHY_LED1_N_JTDI (out), F14 GE2_RXD0 (in), F15 GE2_RXD1 (in), F16 GE1_RXD2 (in), F17 GE1_RXD3 (in), G3 EPHY_LED0_N_JTDO (out), G4 EPHY_LED4_N_JTRST_N (out), G14 GE2_RXD2 (in), G15 GE1_RXDV (in), G16 GE1_RXD0 (in), G17 GE1_RXD1 (in), H13 GE_RGMII_IO_V33D (in), H14 GE2_RXD3 (in), H15 GE1_RXCLK (io), H16 GE1_RXCLK (io), H17 GE1_RXDV (in), J13 GE_RGMII_IO_V33D (in), J14 GE2_TXD1 (out), J15 GE2_TXD0 (out), J16 GE1_TXD0 (out), J17 GE1_TXD1 (out), K14 GE2_TXD3 (out), K15 GE2_TXD2 (out), K16 GE1_TXD2 (out), K17 GE1_TXD3 (out), L14 GE2_TXEN (out), L15 GE2_TXCLK (io), L16 GE1_TXCLK (io), L17 GE1_TXEN (out), M13 EPHY_V12A (in), M14 MDIO (io), M15 MDC (out), M17 EPHY_RES_VBG (io), N12 EPHY_V12A (in), N13 EPHY_V33A (in), N14 MDI_TN_P0 (out), N15 MDI_TP_P0 (out), N16 MDI_RN_P0 (in), N17 MDI_RP_P0 (in), P13 EPHY_V33A (in), P14 MDI_RN_P1 (in), P15 MDI_TP_P2 (out), P16 MDI_TN_P4 (out), P17 MDI_TP_P4 (out), R13 EPHY_V33A (in), R14 MDI_RP_P1 (in), R15 MDI_TN_P2 (out), R16 MDI_RN_P4 (in), R17 MDI_RP_P4 (in), T14 MDI_TN_P1 (out), T15 MDI_RP_P2 (in), T16 MDI_TN_P3 (out), T17 MDI_RN_P3 (in), U14 MDI_TP_P1 (out), U15 MDI_RN_P2 (in), U16 MDI_TP_P3 (out), U17 MDI_RP_P3 (in)
part F pins: A14 VFB_DDR (in), A15 DCDC_V33A (in), A16 DCDC_V33D (in), A17 VFB_DIG (in), B14 EXT_LDO_DDR (out), B15 UGATE (in), B17 EXT_LDO_DIG (out), C11 APCK_VCCA (in), C14 COMP (in), C15 FB (in), D5 BBPLL_V12A (in), D12 PCIE_V33A (in), E5 SOC_IO_V33D_0 (in), E6 BBPLL_V12D (in), E7 SOC_CO_V12D_0 (in), F5 SOC_IO_V33D_1 (in), G5 SOC_CO_V12D_1 (in), G16 LGATE (in), N7 SOC_CO_V12D_2 (in), N8 SOC_CO_V12D_2 (in), N10 SOC_IO_V33D_2 (in), N11 SOC_IO_V33D_2 (in)

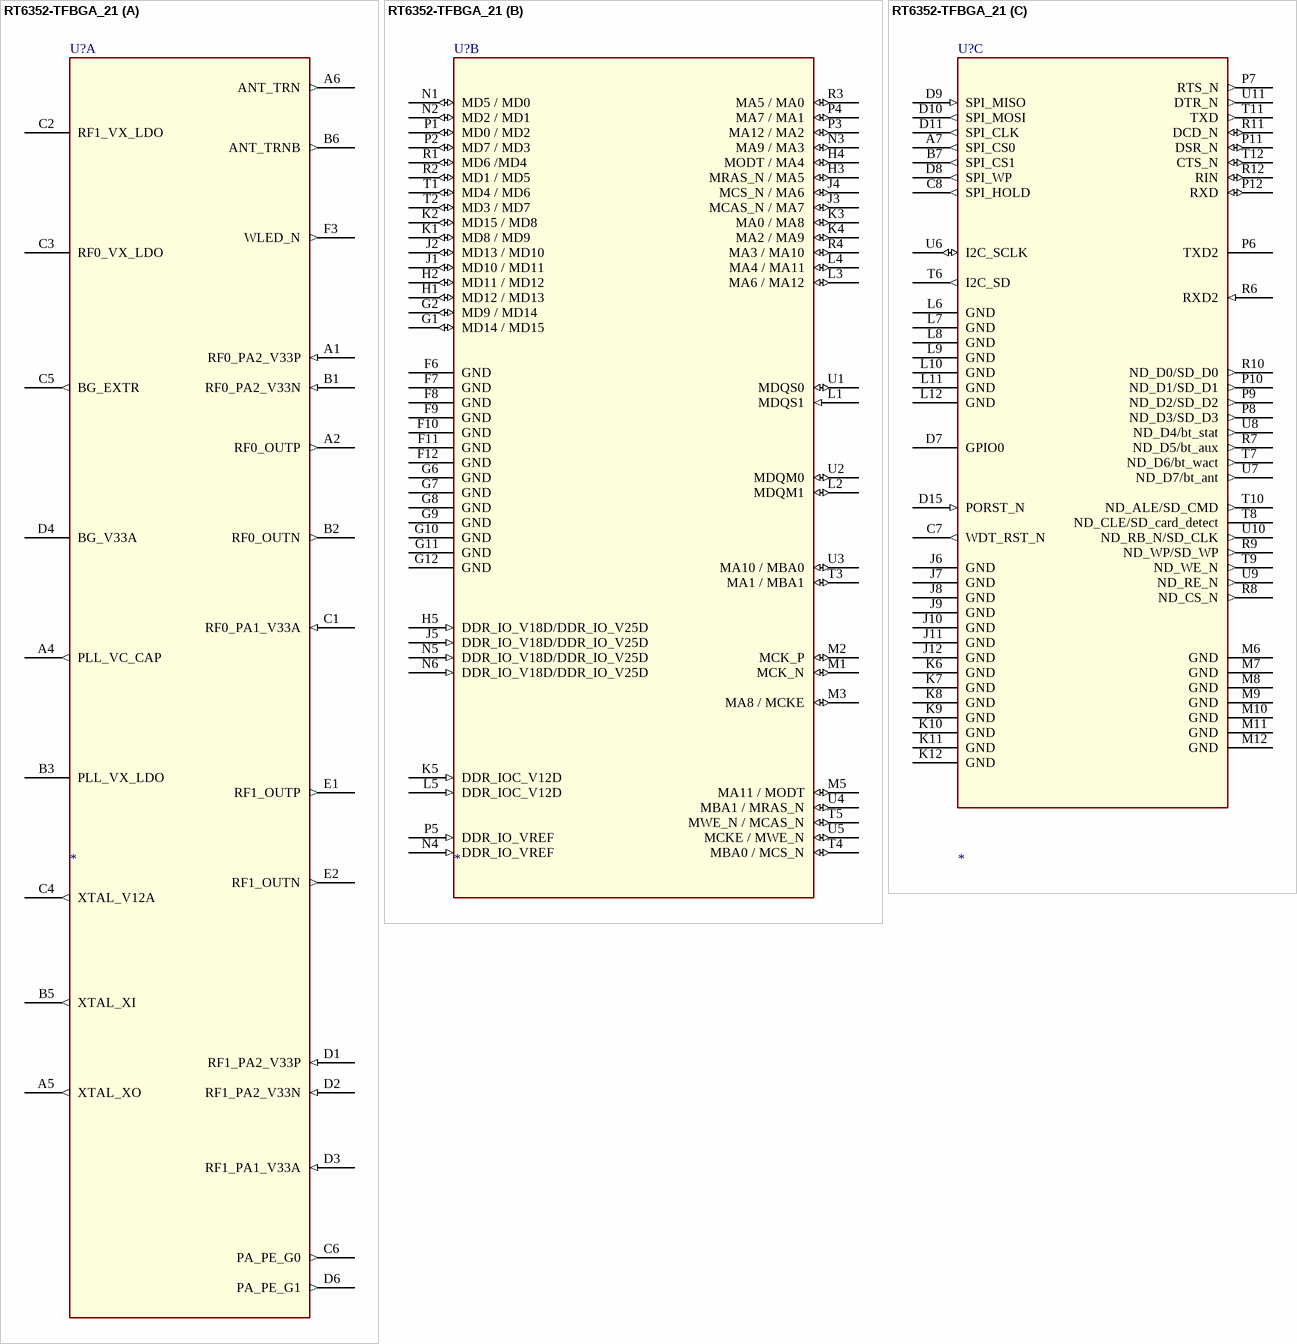
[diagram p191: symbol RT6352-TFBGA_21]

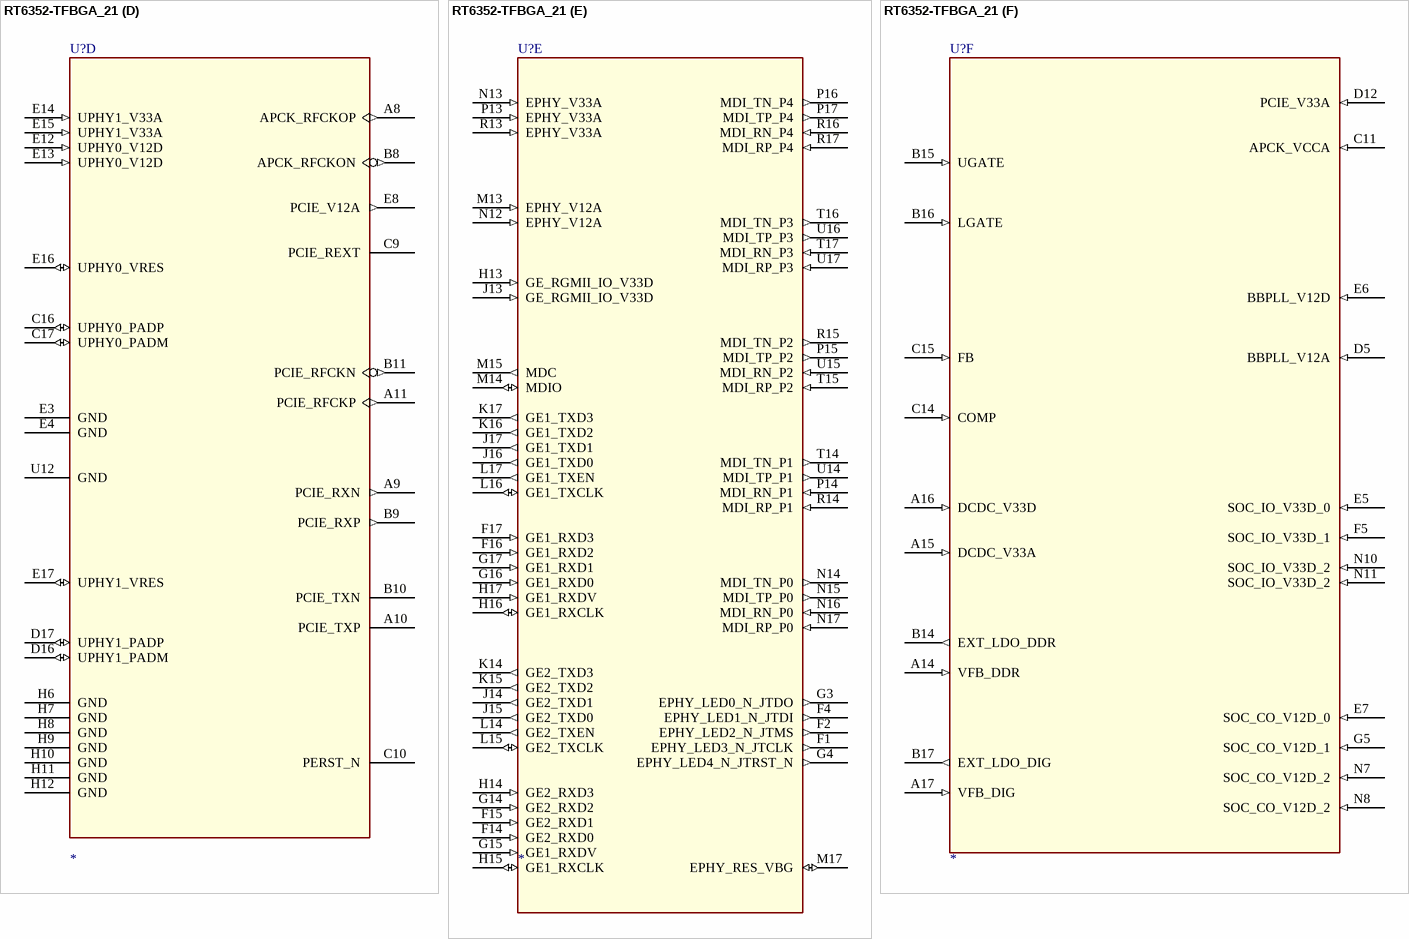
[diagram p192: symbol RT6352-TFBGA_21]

## RT6352-TFBGA_21
designator U?
footprint RT6352/BGA289/P0.65/12X12
part A pins: A1 RF0_PA2_V33P (in), A2 RF0_OUTP (out), A4 PLL_VC_CAP (out), A5 XTAL_XO (out), A6 ANT_TRN (out), B1 RF0_PA2_V33N (in), B2 RF0_OUTN (out), B3 PLL_VX_LDO, B5 XTAL_XI (out), B6 ANT_TRNB (out), C1 RF0_PA1_V33A (in), C2 RF1_VX_LDO, C3 RF0_VX_LDO, C4 XTAL_V12A (out), C5 BG_EXTR (out), C6 PA_PE_G0 (out), D1 RF1_PA2_V33P (in), D2 RF1_PA2_V33N (in), D3 RF1_PA1_V33A (in), D4 BG_V33A, D6 PA_PE_G1 (out), E1 RF1_OUTP (out), E2 RF1_OUTN (out), F3 WLED_N (out)
part B pins: F6 GND (power), F7 GND (power), F8 GND (power), F9 GND (power), F10 GND (power), F11 GND (power), F12 GND (power), G1 MD14 / MD15 (io), G2 MD9 / MD14 (io), G6 GND (power), G7 GND (power), G8 GND (power), G9 GND (power), G10 GND (power), G11 GND (power), G12 GND (power), H1 MD12 / MD13 (io), H2 MD11 / MD12 (io), H3 MRAS_N / MA5 (io), H4 MODT / MA4 (io), H5 DDR_IO_V18D/DDR_IO_V25D (in), J1 MD10 / MD11 (io), J2 MD13 / MD10 (io), J3 MCAS_N / MA7 (io), J4 MCS_N / MA6 (io), J5 DDR_IO_V18D/DDR_IO_V25D (in), K1 MD8 / MD9 (io), K2 MD15 / MD8 (io), K3 MA0 / MA8 (io), K4 MA2 / MA9 (io), K5 DDR_IOC_V12D (in), L1 MDQS1 (in), L2 MDQM1 (io), L3 MA6 / MA12 (io), L4 MA4 / MA11 (io), L5 DDR_IOC_V12D (in), M1 MCK_N (io), M2 MCK_P (io), M3 MA8 / MCKE (io), M5 MA11 / MODT (io), N1 MD5 / MD0 (io), N2 MD2 / MD1 (io), N3 MA9 / MA3 (io), N4 DDR_IO_VREF (in), N5 DDR_IO_V18D/DDR_IO_V25D (in), N6 DDR_IO_V18D/DDR_IO_V25D (in), P1 MD0 / MD2 (io), P2 MD7 / MD3 (io), P3 MA12 / MA2 (io), P4 MA7 / MA1 (io), P5 DDR_IO_VREF (in), R1 MD6 /MD4 (io), R2 MD1 / MD5 (io), R3 MA5 / MA0 (io), R4 MA3 / MA10 (io), T1 MD4 / MD6 (io), T2 MD3 / MD7 (io), T3 MA1 / MBA1 (io), T4 MBA0 / MCS_N (io), T5 MWE_N / MCAS_N (io), U1 MDQS0 (io), U2 MDQM0 (io), U3 MA10 / MBA0 (io), U4 MBA1 / MRAS_N (io), U5 MCKE / MWE_N (io)
part C pins: A7 SPI_CS0 (out), B7 SPI_CS1 (out), C7 WDT_RST_N (out), C8 SPI_HOLD (out), D7 GPIO0, D8 SPI_WP (out), D9 SPI_MISO (in), D10 SPI_MOSI (out), D11 SPI_CLK (out), D15 PORST_N (in), J6 GND (power), J7 GND (power), J8 GND (power), J9 GND (power), J10 GND (power), J11 GND (power), J12 GND (power), K6 GND (power), K7 GND (power), K8 GND (power), K9 GND (power), K10 GND (power), K11 GND (power), K12 GND (power), L6 GND (power), L7 GND (power), L8 GND (power), L9 GND (power), L10 GND (power), L11 GND (power), L12 GND (power), M6 GND (power), M7 GND (power), M8 GND (power), M9 GND (power), M10 GND (power), M11 GND (power), M12 GND (power), P6 TXD2, P7 RTS_N (out), P8 ND_D3/SD_D3 (out), P9 ND_D2/SD_D2 (out), P10 ND_D1/SD_D1 (out), P11 DSR_N (io), P12 RXD (io), R6 RXD2 (in), R7 ND_D5/bt_aux (out), R8 ND_CS_N (out), R9 ND_WP/SD_WP (out), R10 ND_D0/SD_D0 (out), R11 DCD_N (io), R12 RIN (io), T6 I2C_SD (out), T7 ND_D6/bt_wact (out), T8 ND_CLE/SD_card_detect, T9 ND_WE_N (out), T10 ND_ALE/SD_CMD (out), T11 TXD (out), T12 CTS_N (io), U6 I2C_SCLK (io), U7 ND_D7/bt_ant (out), U8 ND_D4/bt_stat (out), U9 ND_RE_N (out), U10 ND_RB_N/SD_CLK (out), U11 DTR_N (out)
part D pins: A8 APCK_RFCKOP (out), A9 PCIE_RXN (out), A10 PCIE_TXP, A11 PCIE_RFCKP (out), B8 APCK_RFCKON (out), B9 PCIE_RXP (out), B10 PCIE_TXN, B11 PCIE_RFCKN (out), C9 PCIE_REXT, C10 PERST_N, C16 UPHY0_PADP (io), C17 UPHY0_PADM (io), D16 UPHY1_PADM (io), D17 UPHY1_PADP (io), E3 GND, E4 GND, E8 PCIE_V12A (out), E12 UPHY0_V12D (in), E13 UPHY0_V12D (in), E14 UPHY1_V33A (in), E15 UPHY1_V33A (in), E16 UPHY0_VRES (io), E17 UPHY1_VRES (io), H6 GND (power), H7 GND (power), H8 GND (power), H9 GND (power), H10 GND (power), H11 GND (power), H12 GND (power), U12 GND
part E pins: F1 EPHY_LED3_N_JTCLK (out), F2 EPHY_LED2_N_JTMS (out), F4 EPHY_LED1_N_JTDI (out), F14 GE2_RXD0 (in), F15 GE2_RXD1 (in), F16 GE1_RXD2 (in), F17 GE1_RXD3 (in), G3 EPHY_LED0_N_JTDO (out), G4 EPHY_LED4_N_JTRST_N (out), G14 GE2_RXD2 (in), G15 GE1_RXDV (in), G16 GE1_RXD0 (in), G17 GE1_RXD1 (in), H13 GE_RGMII_IO_V33D (in), H14 GE2_RXD3 (in), H15 GE1_RXCLK (io), H16 GE1_RXCLK (io), H17 GE1_RXDV (in), J13 GE_RGMII_IO_V33D (in), J14 GE2_TXD1 (out), J15 GE2_TXD0 (out), J16 GE1_TXD0 (out), J17 GE1_TXD1 (out), K14 GE2_TXD3 (out), K15 GE2_TXD2 (out), K16 GE1_TXD2 (out), K17 GE1_TXD3 (out), L14 GE2_TXEN (out), L15 GE2_TXCLK (io), L16 GE1_TXCLK (io), L17 GE1_TXEN (out), M13 EPHY_V12A (in), M14 MDIO (io), M15 MDC (out), M17 EPHY_RES_VBG (io), N12 EPHY_V12A (in), N13 EPHY_V33A (in), N14 MDI_TN_P0 (out), N15 MDI_TP_P0 (out), N16 MDI_RN_P0 (in), N17 MDI_RP_P0 (in), P13 EPHY_V33A (in), P14 MDI_RN_P1 (in), P15 MDI_TP_P2 (out), P16 MDI_TN_P4 (out), P17 MDI_TP_P4 (out), R13 EPHY_V33A (in), R14 MDI_RP_P1 (in), R15 MDI_TN_P2 (out), R16 MDI_RN_P4 (in), R17 MDI_RP_P4 (in), T14 MDI_TN_P1 (out), T15 MDI_RP_P2 (in), T16 MDI_TN_P3 (out), T17 MDI_RN_P3 (in), U14 MDI_TP_P1 (out), U15 MDI_RN_P2 (in), U16 MDI_TP_P3 (out), U17 MDI_RP_P3 (in)
part F pins: A14 VFB_DDR (in), A15 DCDC_V33A (in), A16 DCDC_V33D (in), A17 VFB_DIG (in), B14 EXT_LDO_DDR (out), B15 UGATE (in), B16 LGATE (in), B17 EXT_LDO_DIG (out), C11 APCK_VCCA (in), C14 COMP (in), C15 FB (in), D5 BBPLL_V12A (in), D12 PCIE_V33A (in), E5 SOC_IO_V33D_0 (in), E6 BBPLL_V12D (in), E7 SOC_CO_V12D_0 (in), F5 SOC_IO_V33D_1 (in), G5 SOC_CO_V12D_1 (in), N7 SOC_CO_V12D_2 (in), N8 SOC_CO_V12D_2 (in), N10 SOC_IO_V33D_2 (in), N11 SOC_IO_V33D_2 (in)

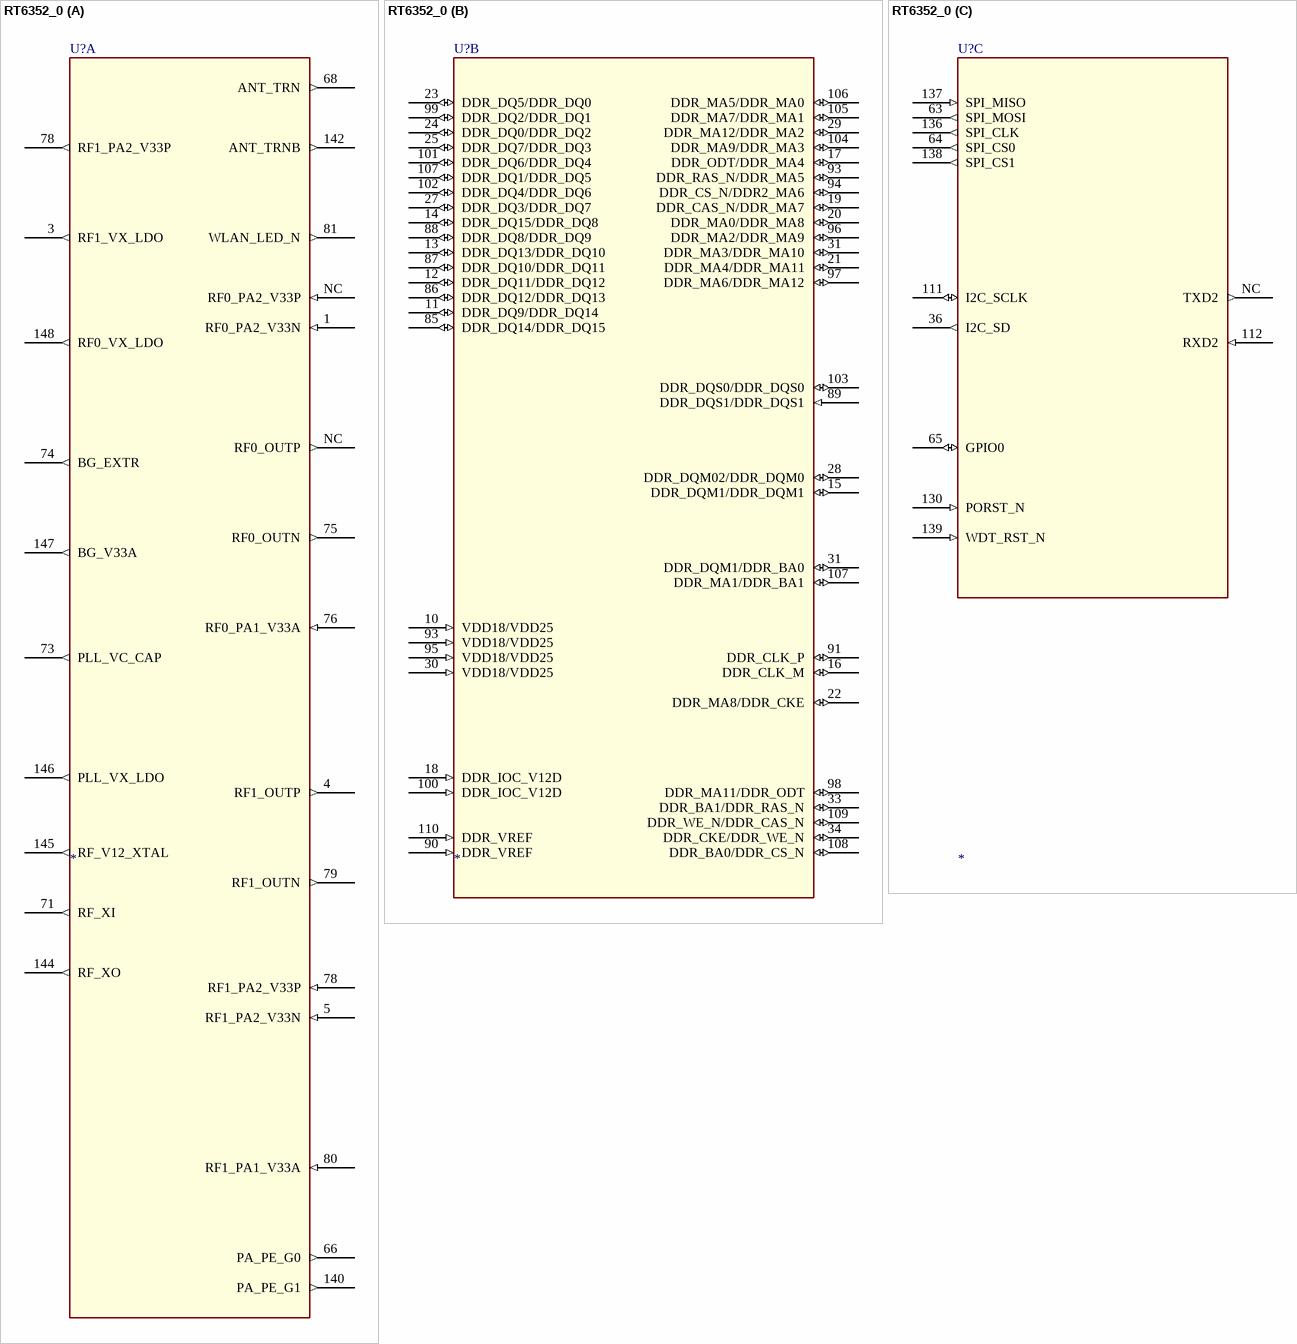
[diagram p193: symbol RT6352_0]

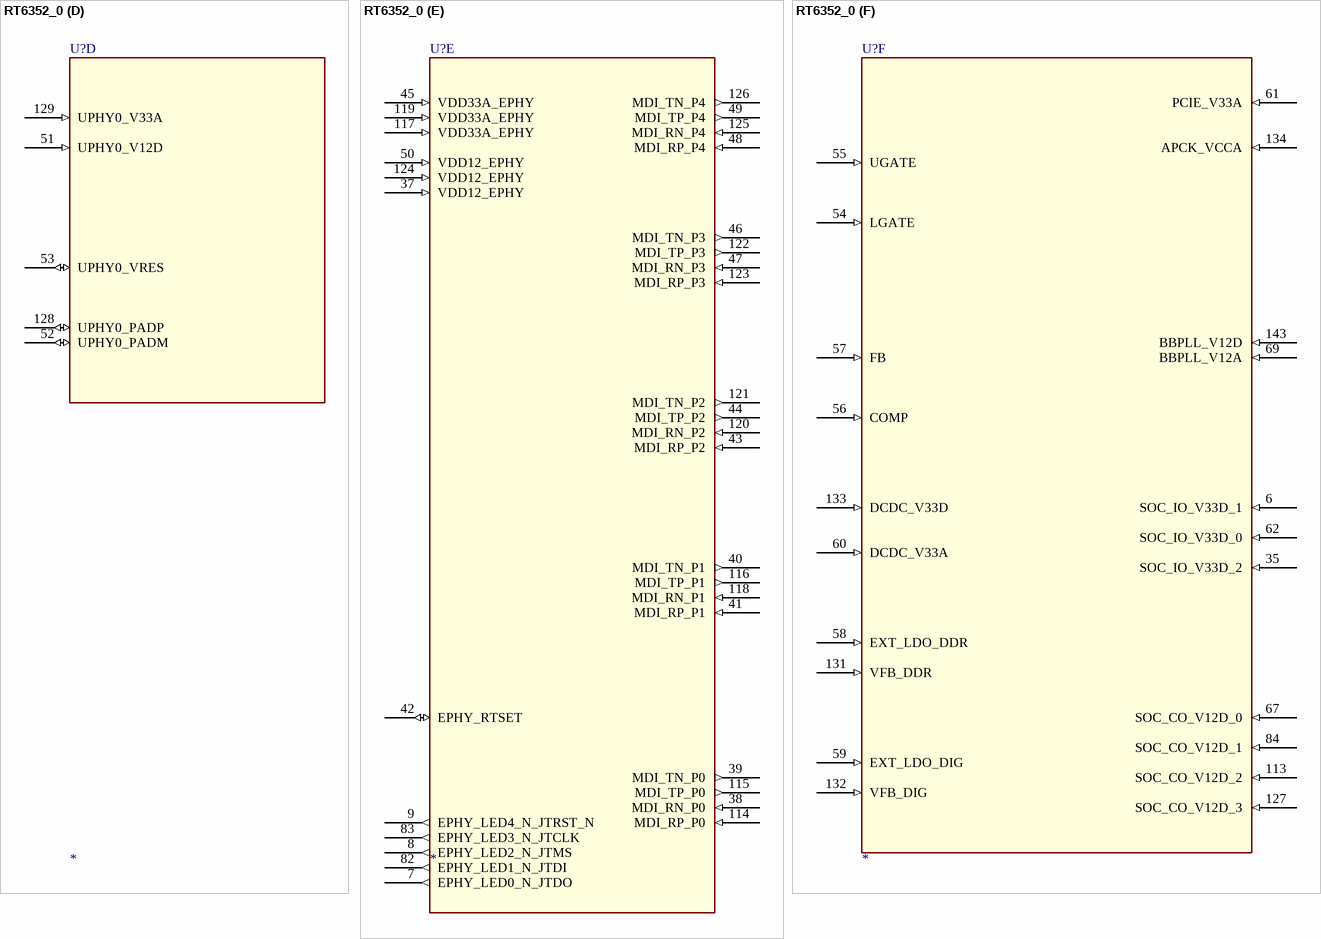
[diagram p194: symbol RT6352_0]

## RT6352_0
designator U?
footprint DRQFN148
part A pins: 1 RF0_PA2_V33N (in), 3 RF1_VX_LDO (out), 4 RF1_OUTP (out), 5 RF1_PA2_V33N (in), 66 PA_PE_G0 (out), 68 ANT_TRN (out), 71 RF_XI (out), 73 PLL_VC_CAP (out), 74 BG_EXTR (out), 75 RF0_OUTN (out), 76 RF0_PA1_V33A (in), 78 RF1_PA2_V33P (out), 78 RF1_PA2_V33P (in), 79 RF1_OUTN (out), 80 RF1_PA1_V33A (in), 81 WLAN_LED_N (out), 140 PA_PE_G1 (out), 142 ANT_TRNB (out), 144 RF_XO (out), 145 RF_V12_XTAL (out), 146 PLL_VX_LDO (out), 147 BG_V33A (out), 148 RF0_VX_LDO (out), NC RF0_OUTP (out), NC RF0_PA2_V33P (in)
part B pins: 10 VDD18/VDD25 (in), 11 DDR_DQ9/DDR_DQ14 (io), 12 DDR_DQ11/DDR_DQ12 (io), 13 DDR_DQ13/DDR_DQ10 (io), 14 DDR_DQ15/DDR_DQ8 (io), 15 DDR_DQM1/DDR_DQM1 (io), 16 DDR_CLK_M (io), 17 DDR_ODT/DDR_MA4 (io), 18 DDR_IOC_V12D (in), 19 DDR_CAS_N/DDR_MA7 (io), 20 DDR_MA0/DDR_MA8 (io), 21 DDR_MA4/DDR_MA11 (io), 22 DDR_MA8/DDR_CKE (io), 23 DDR_DQ5/DDR_DQ0 (io), 24 DDR_DQ0/DDR_DQ2 (io), 25 DDR_DQ7/DDR_DQ3 (io), 27 DDR_DQ3/DDR_DQ7 (io), 28 DDR_DQM02/DDR_DQM0 (io), 29 DDR_MA12/DDR_MA2 (io), 30 VDD18/VDD25 (in), 31 DDR_MA3/DDR_MA10 (io), 31 DDR_DQM1/DDR_BA0 (io), 33 DDR_BA1/DDR_RAS_N (io), 34 DDR_CKE/DDR_WE_N (io), 85 DDR_DQ14/DDR_DQ15 (io), 86 DDR_DQ12/DDR_DQ13 (io), 87 DDR_DQ10/DDR_DQ11 (io), 88 DDR_DQ8/DDR_DQ9 (io), 89 DDR_DQS1/DDR_DQS1 (in), 90 DDR_VREF (in), 91 DDR_CLK_P (io), 93 DDR_RAS_N/DDR_MA5 (io), 93 VDD18/VDD25 (in), 94 DDR_CS_N/DDR2_MA6 (io), 95 VDD18/VDD25 (in), 96 DDR_MA2/DDR_MA9 (io), 97 DDR_MA6/DDR_MA12 (io), 98 DDR_MA11/DDR_ODT (io), 99 DDR_DQ2/DDR_DQ1 (io), 100 DDR_IOC_V12D (in), 101 DDR_DQ6/DDR_DQ4 (io), 102 DDR_DQ4/DDR_DQ6 (io), 103 DDR_DQS0/DDR_DQS0 (io), 104 DDR_MA9/DDR_MA3 (io), 105 DDR_MA7/DDR_MA1 (io), 106 DDR_MA5/DDR_MA0 (io), 107 DDR_DQ1/DDR_DQ5 (io), 107 DDR_MA1/DDR_BA1 (io), 108 DDR_BA0/DDR_CS_N (io), 109 DDR_WE_N/DDR_CAS_N (io), 110 DDR_VREF (in)
part C pins: 36 I2C_SD (out), 63 SPI_MOSI (out), 64 SPI_CS0 (out), 65 GPIO0 (io), 111 I2C_SCLK (io), 112 RXD2 (in), 130 PORST_N (in), 136 SPI_CLK (out), 137 SPI_MISO (in), 138 SPI_CS1 (out), 139 WDT_RST_N (in), NC TXD2 (out)
part D pins: 51 UPHY0_V12D (in), 52 UPHY0_PADM (io), 53 UPHY0_VRES (io), 128 UPHY0_PADP (io), 129 UPHY0_V33A (in)
part E pins: 7 EPHY_LED0_N_JTDO (out), 8 EPHY_LED2_N_JTMS (out), 9 EPHY_LED4_N_JTRST_N (out), 37 VDD12_EPHY (in), 38 MDI_RN_P0 (in), 39 MDI_TN_P0 (out), 40 MDI_TN_P1 (out), 41 MDI_RP_P1 (in), 42 EPHY_RTSET (io), 43 MDI_RP_P2 (in), 44 MDI_TP_P2 (out), 45 VDD33A_EPHY (in), 46 MDI_TN_P3 (out), 47 MDI_RN_P3 (in), 48 MDI_RP_P4 (in), 49 MDI_TP_P4 (out), 50 VDD12_EPHY (in), 82 EPHY_LED1_N_JTDI (out), 83 EPHY_LED3_N_JTCLK (out), 114 MDI_RP_P0 (in), 115 MDI_TP_P0 (out), 116 MDI_TP_P1 (out), 117 VDD33A_EPHY (in), 118 MDI_RN_P1 (in), 119 VDD33A_EPHY (in), 120 MDI_RN_P2 (in), 121 MDI_TN_P2 (out), 122 MDI_TP_P3 (out), 123 MDI_RP_P3 (in), 124 VDD12_EPHY (in), 125 MDI_RN_P4 (in), 126 MDI_TN_P4 (out)
part F pins: 6 SOC_IO_V33D_1 (in), 35 SOC_IO_V33D_2 (in), 54 LGATE (in), 55 UGATE (in), 56 COMP (in), 57 FB (in), 58 EXT_LDO_DDR (in), 59 EXT_LDO_DIG (in), 60 DCDC_V33A (in), 61 PCIE_V33A (in), 62 SOC_IO_V33D_0 (in), 67 SOC_CO_V12D_0 (in), 69 BBPLL_V12A (in), 84 SOC_CO_V12D_1 (in), 113 SOC_CO_V12D_2 (in), 127 SOC_CO_V12D_3 (in), 131 VFB_DDR (in), 132 VFB_DIG (in), 133 DCDC_V33D (in), 134 APCK_VCCA (in), 143 BBPLL_V12D (in)

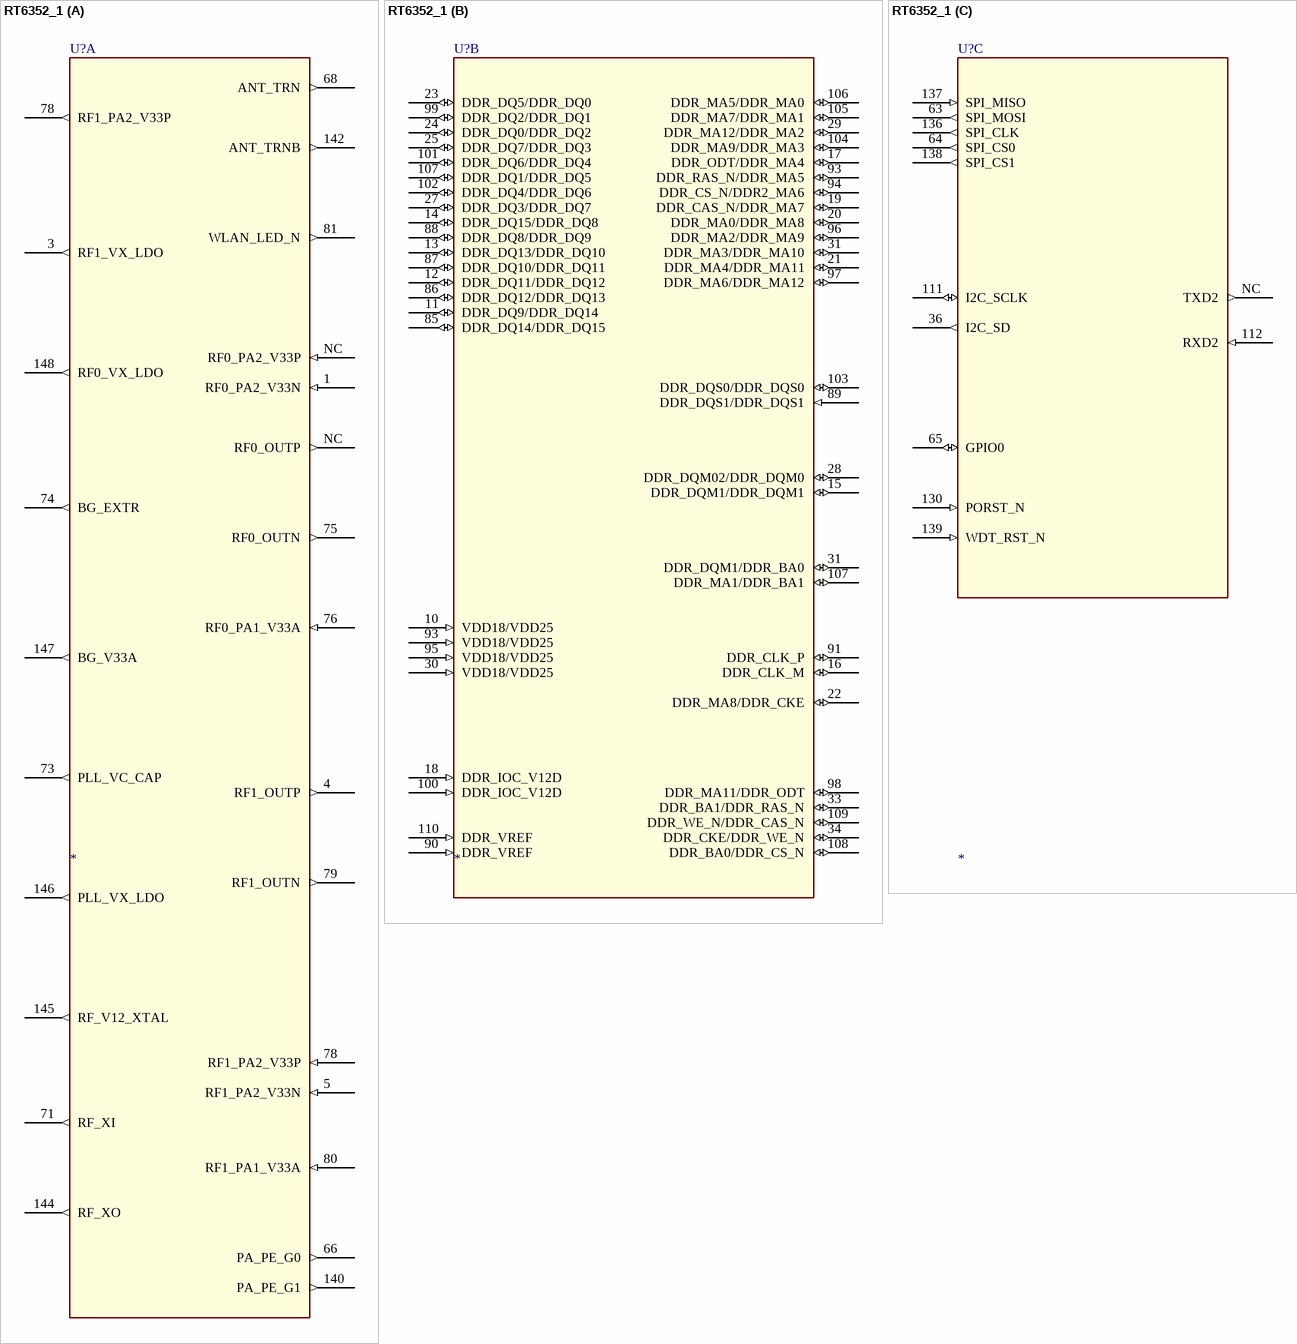
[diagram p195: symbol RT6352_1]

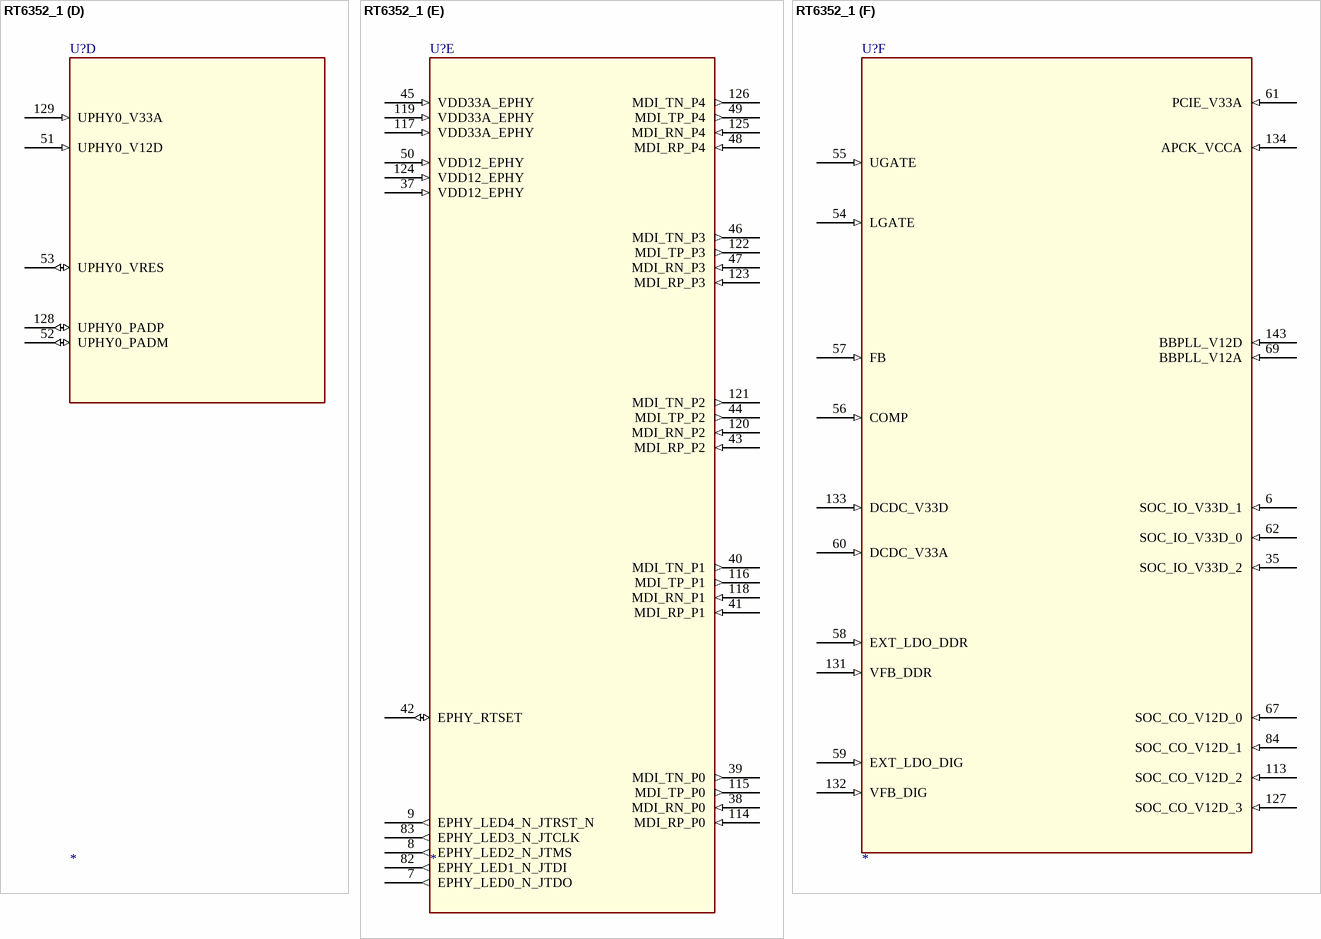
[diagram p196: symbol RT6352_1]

## RT6352_1
designator U?
footprint DRQFN148
part A pins: 1 RF0_PA2_V33N (in), 3 RF1_VX_LDO (out), 4 RF1_OUTP (out), 5 RF1_PA2_V33N (in), 66 PA_PE_G0 (out), 68 ANT_TRN (out), 71 RF_XI (out), 73 PLL_VC_CAP (out), 74 BG_EXTR (out), 75 RF0_OUTN (out), 76 RF0_PA1_V33A (in), 78 RF1_PA2_V33P (out), 78 RF1_PA2_V33P (in), 79 RF1_OUTN (out), 80 RF1_PA1_V33A (in), 81 WLAN_LED_N (out), 140 PA_PE_G1 (out), 142 ANT_TRNB (out), 144 RF_XO (out), 145 RF_V12_XTAL (out), 146 PLL_VX_LDO (out), 147 BG_V33A (out), 148 RF0_VX_LDO (out), NC RF0_OUTP (out), NC RF0_PA2_V33P (in)
part B pins: 10 VDD18/VDD25 (in), 11 DDR_DQ9/DDR_DQ14 (io), 12 DDR_DQ11/DDR_DQ12 (io), 13 DDR_DQ13/DDR_DQ10 (io), 14 DDR_DQ15/DDR_DQ8 (io), 15 DDR_DQM1/DDR_DQM1 (io), 16 DDR_CLK_M (io), 17 DDR_ODT/DDR_MA4 (io), 18 DDR_IOC_V12D (in), 19 DDR_CAS_N/DDR_MA7 (io), 20 DDR_MA0/DDR_MA8 (io), 21 DDR_MA4/DDR_MA11 (io), 22 DDR_MA8/DDR_CKE (io), 23 DDR_DQ5/DDR_DQ0 (io), 24 DDR_DQ0/DDR_DQ2 (io), 25 DDR_DQ7/DDR_DQ3 (io), 27 DDR_DQ3/DDR_DQ7 (io), 28 DDR_DQM02/DDR_DQM0 (io), 29 DDR_MA12/DDR_MA2 (io), 30 VDD18/VDD25 (in), 31 DDR_MA3/DDR_MA10 (io), 31 DDR_DQM1/DDR_BA0 (io), 33 DDR_BA1/DDR_RAS_N (io), 34 DDR_CKE/DDR_WE_N (io), 85 DDR_DQ14/DDR_DQ15 (io), 86 DDR_DQ12/DDR_DQ13 (io), 87 DDR_DQ10/DDR_DQ11 (io), 88 DDR_DQ8/DDR_DQ9 (io), 89 DDR_DQS1/DDR_DQS1 (in), 90 DDR_VREF (in), 91 DDR_CLK_P (io), 93 DDR_RAS_N/DDR_MA5 (io), 93 VDD18/VDD25 (in), 94 DDR_CS_N/DDR2_MA6 (io), 95 VDD18/VDD25 (in), 96 DDR_MA2/DDR_MA9 (io), 97 DDR_MA6/DDR_MA12 (io), 98 DDR_MA11/DDR_ODT (io), 99 DDR_DQ2/DDR_DQ1 (io), 100 DDR_IOC_V12D (in), 101 DDR_DQ6/DDR_DQ4 (io), 102 DDR_DQ4/DDR_DQ6 (io), 103 DDR_DQS0/DDR_DQS0 (io), 104 DDR_MA9/DDR_MA3 (io), 105 DDR_MA7/DDR_MA1 (io), 106 DDR_MA5/DDR_MA0 (io), 107 DDR_DQ1/DDR_DQ5 (io), 107 DDR_MA1/DDR_BA1 (io), 108 DDR_BA0/DDR_CS_N (io), 109 DDR_WE_N/DDR_CAS_N (io), 110 DDR_VREF (in)
part C pins: 36 I2C_SD (out), 63 SPI_MOSI (out), 64 SPI_CS0 (out), 65 GPIO0 (io), 111 I2C_SCLK (io), 112 RXD2 (in), 130 PORST_N (in), 136 SPI_CLK (out), 137 SPI_MISO (in), 138 SPI_CS1 (out), 139 WDT_RST_N (in), NC TXD2 (out)
part D pins: 51 UPHY0_V12D (in), 52 UPHY0_PADM (io), 53 UPHY0_VRES (io), 128 UPHY0_PADP (io), 129 UPHY0_V33A (in)
part E pins: 7 EPHY_LED0_N_JTDO (out), 8 EPHY_LED2_N_JTMS (out), 9 EPHY_LED4_N_JTRST_N (out), 37 VDD12_EPHY (in), 38 MDI_RN_P0 (in), 39 MDI_TN_P0 (out), 40 MDI_TN_P1 (out), 41 MDI_RP_P1 (in), 42 EPHY_RTSET (io), 43 MDI_RP_P2 (in), 44 MDI_TP_P2 (out), 45 VDD33A_EPHY (in), 46 MDI_TN_P3 (out), 47 MDI_RN_P3 (in), 48 MDI_RP_P4 (in), 49 MDI_TP_P4 (out), 50 VDD12_EPHY (in), 82 EPHY_LED1_N_JTDI (out), 83 EPHY_LED3_N_JTCLK (out), 114 MDI_RP_P0 (in), 115 MDI_TP_P0 (out), 116 MDI_TP_P1 (out), 117 VDD33A_EPHY (in), 118 MDI_RN_P1 (in), 119 VDD33A_EPHY (in), 120 MDI_RN_P2 (in), 121 MDI_TN_P2 (out), 122 MDI_TP_P3 (out), 123 MDI_RP_P3 (in), 124 VDD12_EPHY (in), 125 MDI_RN_P4 (in), 126 MDI_TN_P4 (out)
part F pins: 6 SOC_IO_V33D_1 (in), 35 SOC_IO_V33D_2 (in), 54 LGATE (in), 55 UGATE (in), 56 COMP (in), 57 FB (in), 58 EXT_LDO_DDR (in), 59 EXT_LDO_DIG (in), 60 DCDC_V33A (in), 61 PCIE_V33A (in), 62 SOC_IO_V33D_0 (in), 67 SOC_CO_V12D_0 (in), 69 BBPLL_V12A (in), 84 SOC_CO_V12D_1 (in), 113 SOC_CO_V12D_2 (in), 127 SOC_CO_V12D_3 (in), 131 VFB_DDR (in), 132 VFB_DIG (in), 133 DCDC_V33D (in), 134 APCK_VCCA (in), 143 BBPLL_V12D (in)

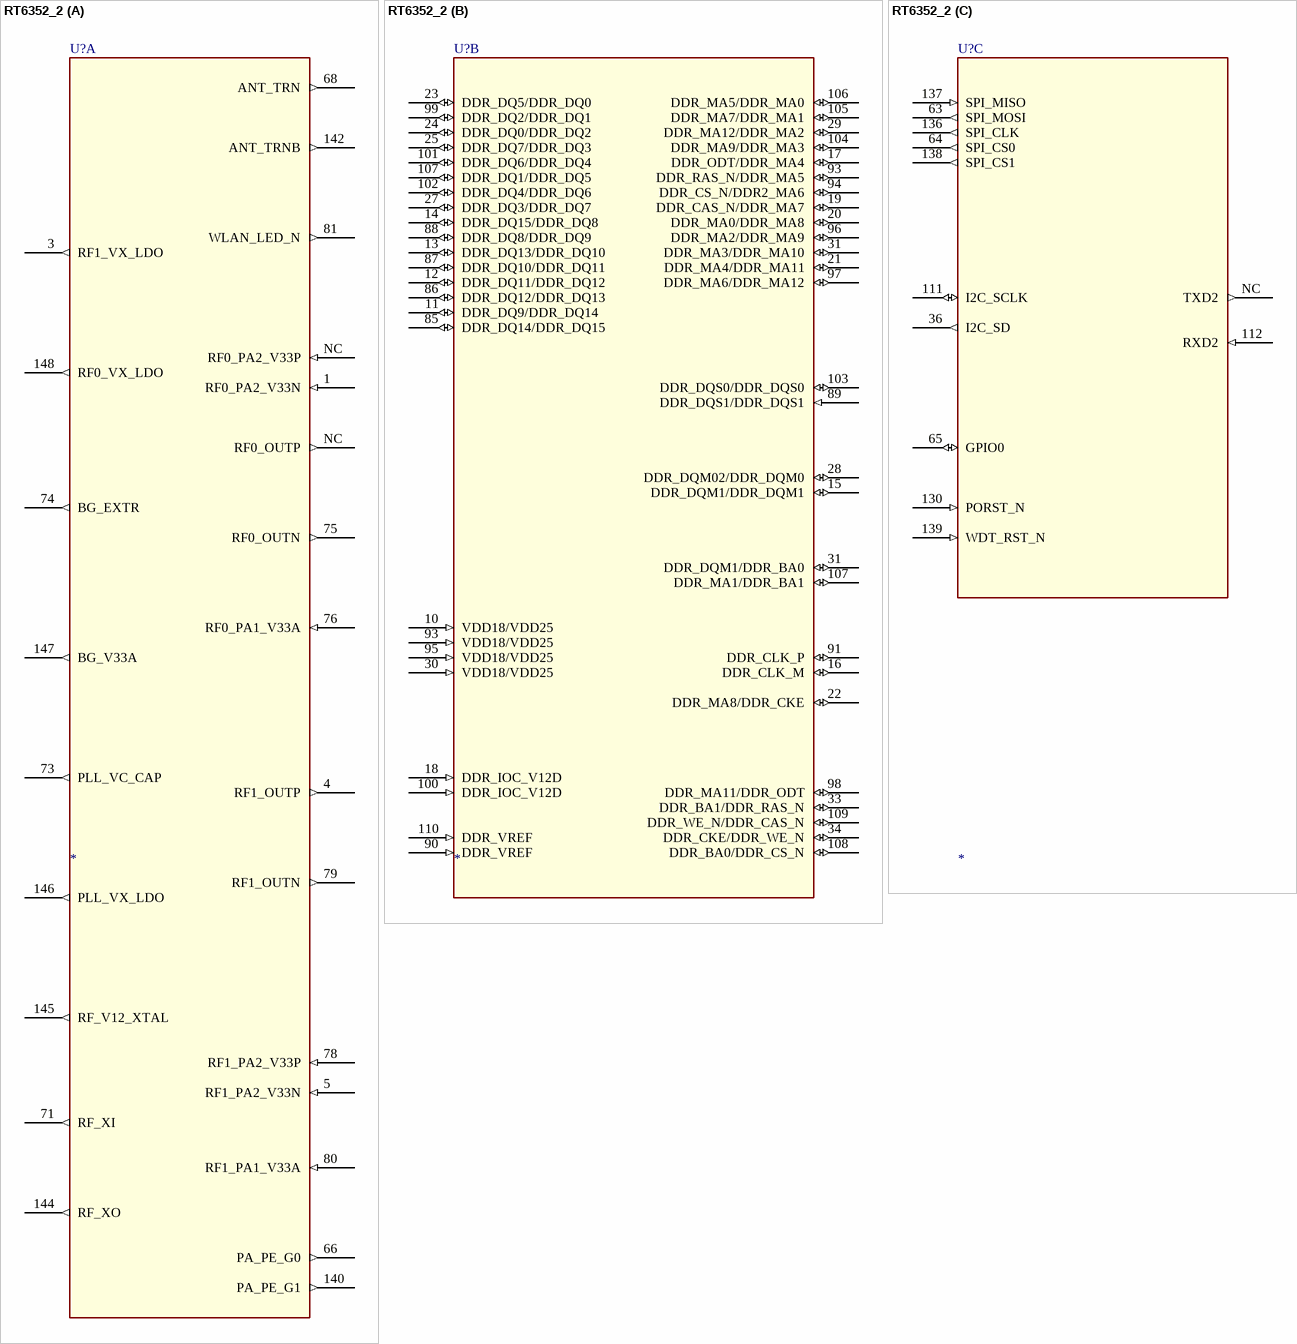
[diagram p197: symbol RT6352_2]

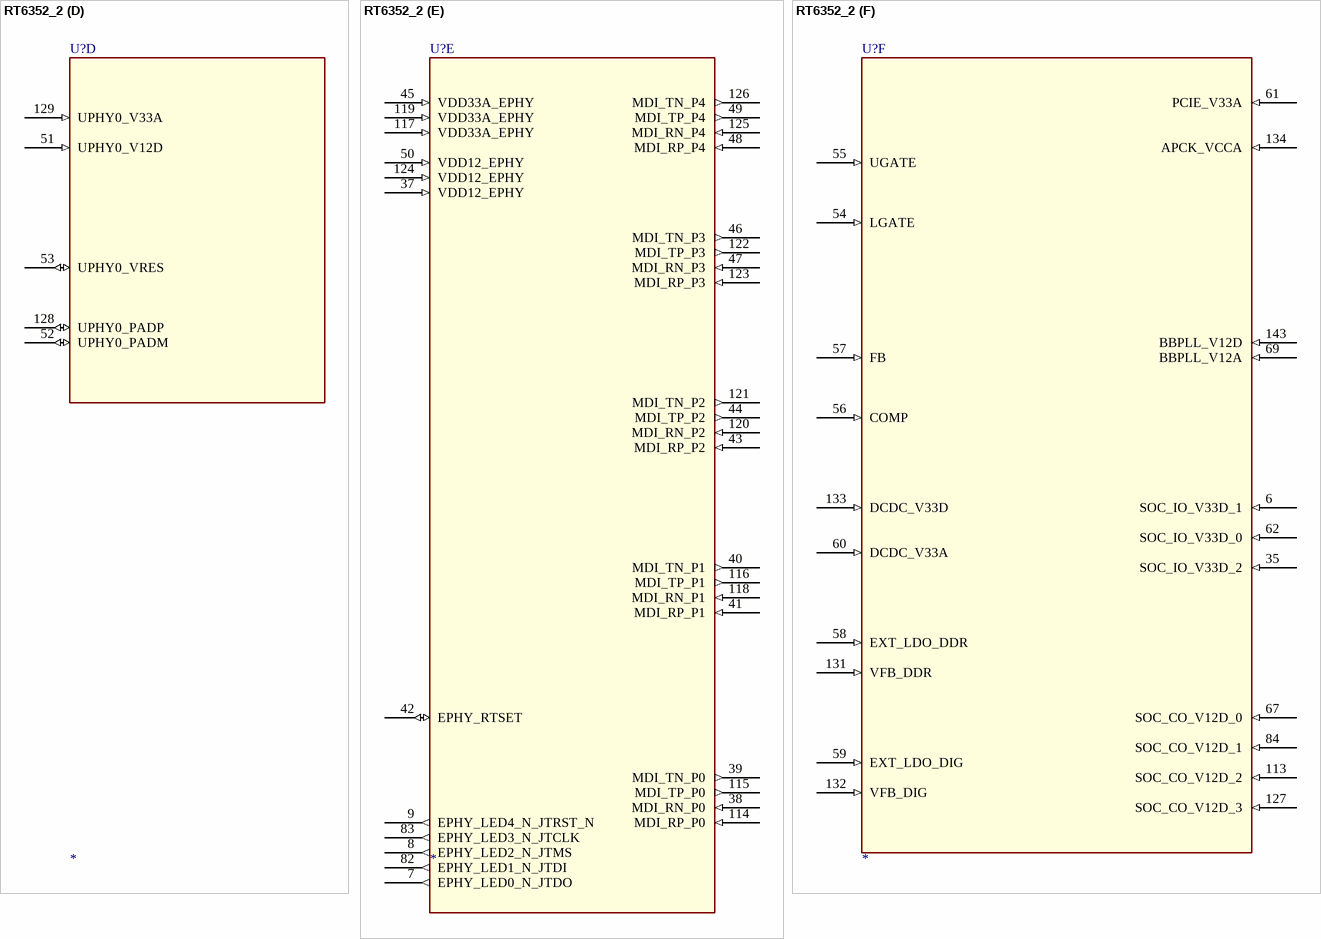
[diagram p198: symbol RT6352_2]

## RT6352_2
designator U?
footprint DRQFN148
part A pins: 1 RF0_PA2_V33N (in), 3 RF1_VX_LDO (out), 4 RF1_OUTP (out), 5 RF1_PA2_V33N (in), 66 PA_PE_G0 (out), 68 ANT_TRN (out), 71 RF_XI (out), 73 PLL_VC_CAP (out), 74 BG_EXTR (out), 75 RF0_OUTN (out), 76 RF0_PA1_V33A (in), 78 RF1_PA2_V33P (in), 79 RF1_OUTN (out), 80 RF1_PA1_V33A (in), 81 WLAN_LED_N (out), 140 PA_PE_G1 (out), 142 ANT_TRNB (out), 144 RF_XO (out), 145 RF_V12_XTAL (out), 146 PLL_VX_LDO (out), 147 BG_V33A (out), 148 RF0_VX_LDO (out), NC RF0_OUTP (out), NC RF0_PA2_V33P (in)
part B pins: 10 VDD18/VDD25 (in), 11 DDR_DQ9/DDR_DQ14 (io), 12 DDR_DQ11/DDR_DQ12 (io), 13 DDR_DQ13/DDR_DQ10 (io), 14 DDR_DQ15/DDR_DQ8 (io), 15 DDR_DQM1/DDR_DQM1 (io), 16 DDR_CLK_M (io), 17 DDR_ODT/DDR_MA4 (io), 18 DDR_IOC_V12D (in), 19 DDR_CAS_N/DDR_MA7 (io), 20 DDR_MA0/DDR_MA8 (io), 21 DDR_MA4/DDR_MA11 (io), 22 DDR_MA8/DDR_CKE (io), 23 DDR_DQ5/DDR_DQ0 (io), 24 DDR_DQ0/DDR_DQ2 (io), 25 DDR_DQ7/DDR_DQ3 (io), 27 DDR_DQ3/DDR_DQ7 (io), 28 DDR_DQM02/DDR_DQM0 (io), 29 DDR_MA12/DDR_MA2 (io), 30 VDD18/VDD25 (in), 31 DDR_MA3/DDR_MA10 (io), 31 DDR_DQM1/DDR_BA0 (io), 33 DDR_BA1/DDR_RAS_N (io), 34 DDR_CKE/DDR_WE_N (io), 85 DDR_DQ14/DDR_DQ15 (io), 86 DDR_DQ12/DDR_DQ13 (io), 87 DDR_DQ10/DDR_DQ11 (io), 88 DDR_DQ8/DDR_DQ9 (io), 89 DDR_DQS1/DDR_DQS1 (in), 90 DDR_VREF (in), 91 DDR_CLK_P (io), 93 DDR_RAS_N/DDR_MA5 (io), 93 VDD18/VDD25 (in), 94 DDR_CS_N/DDR2_MA6 (io), 95 VDD18/VDD25 (in), 96 DDR_MA2/DDR_MA9 (io), 97 DDR_MA6/DDR_MA12 (io), 98 DDR_MA11/DDR_ODT (io), 99 DDR_DQ2/DDR_DQ1 (io), 100 DDR_IOC_V12D (in), 101 DDR_DQ6/DDR_DQ4 (io), 102 DDR_DQ4/DDR_DQ6 (io), 103 DDR_DQS0/DDR_DQS0 (io), 104 DDR_MA9/DDR_MA3 (io), 105 DDR_MA7/DDR_MA1 (io), 106 DDR_MA5/DDR_MA0 (io), 107 DDR_DQ1/DDR_DQ5 (io), 107 DDR_MA1/DDR_BA1 (io), 108 DDR_BA0/DDR_CS_N (io), 109 DDR_WE_N/DDR_CAS_N (io), 110 DDR_VREF (in)
part C pins: 36 I2C_SD (out), 63 SPI_MOSI (out), 64 SPI_CS0 (out), 65 GPIO0 (io), 111 I2C_SCLK (io), 112 RXD2 (in), 130 PORST_N (in), 136 SPI_CLK (out), 137 SPI_MISO (in), 138 SPI_CS1 (out), 139 WDT_RST_N (in), NC TXD2 (out)
part D pins: 51 UPHY0_V12D (in), 52 UPHY0_PADM (io), 53 UPHY0_VRES (io), 128 UPHY0_PADP (io), 129 UPHY0_V33A (in)
part E pins: 7 EPHY_LED0_N_JTDO (out), 8 EPHY_LED2_N_JTMS (out), 9 EPHY_LED4_N_JTRST_N (out), 37 VDD12_EPHY (in), 38 MDI_RN_P0 (in), 39 MDI_TN_P0 (out), 40 MDI_TN_P1 (out), 41 MDI_RP_P1 (in), 42 EPHY_RTSET (io), 43 MDI_RP_P2 (in), 44 MDI_TP_P2 (out), 45 VDD33A_EPHY (in), 46 MDI_TN_P3 (out), 47 MDI_RN_P3 (in), 48 MDI_RP_P4 (in), 49 MDI_TP_P4 (out), 50 VDD12_EPHY (in), 82 EPHY_LED1_N_JTDI (out), 83 EPHY_LED3_N_JTCLK (out), 114 MDI_RP_P0 (in), 115 MDI_TP_P0 (out), 116 MDI_TP_P1 (out), 117 VDD33A_EPHY (in), 118 MDI_RN_P1 (in), 119 VDD33A_EPHY (in), 120 MDI_RN_P2 (in), 121 MDI_TN_P2 (out), 122 MDI_TP_P3 (out), 123 MDI_RP_P3 (in), 124 VDD12_EPHY (in), 125 MDI_RN_P4 (in), 126 MDI_TN_P4 (out)
part F pins: 6 SOC_IO_V33D_1 (in), 35 SOC_IO_V33D_2 (in), 54 LGATE (in), 55 UGATE (in), 56 COMP (in), 57 FB (in), 58 EXT_LDO_DDR (in), 59 EXT_LDO_DIG (in), 60 DCDC_V33A (in), 61 PCIE_V33A (in), 62 SOC_IO_V33D_0 (in), 67 SOC_CO_V12D_0 (in), 69 BBPLL_V12A (in), 84 SOC_CO_V12D_1 (in), 113 SOC_CO_V12D_2 (in), 127 SOC_CO_V12D_3 (in), 131 VFB_DDR (in), 132 VFB_DIG (in), 133 DCDC_V33D (in), 134 APCK_VCCA (in), 143 BBPLL_V12D (in)

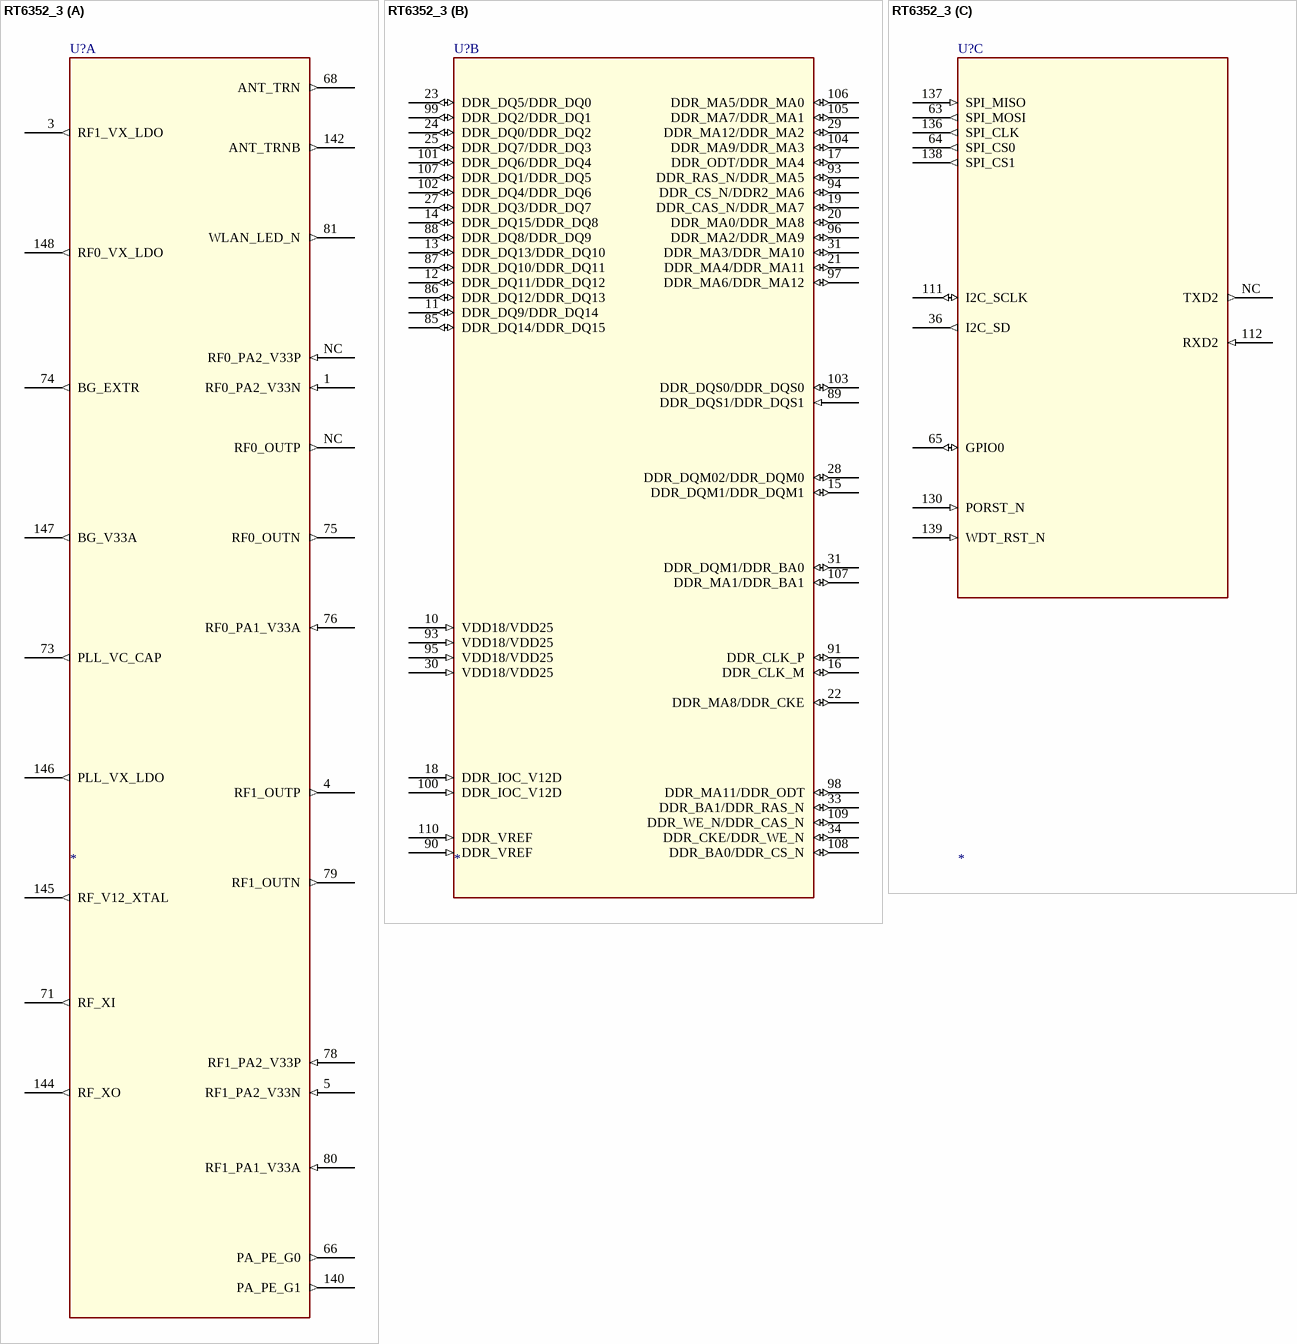
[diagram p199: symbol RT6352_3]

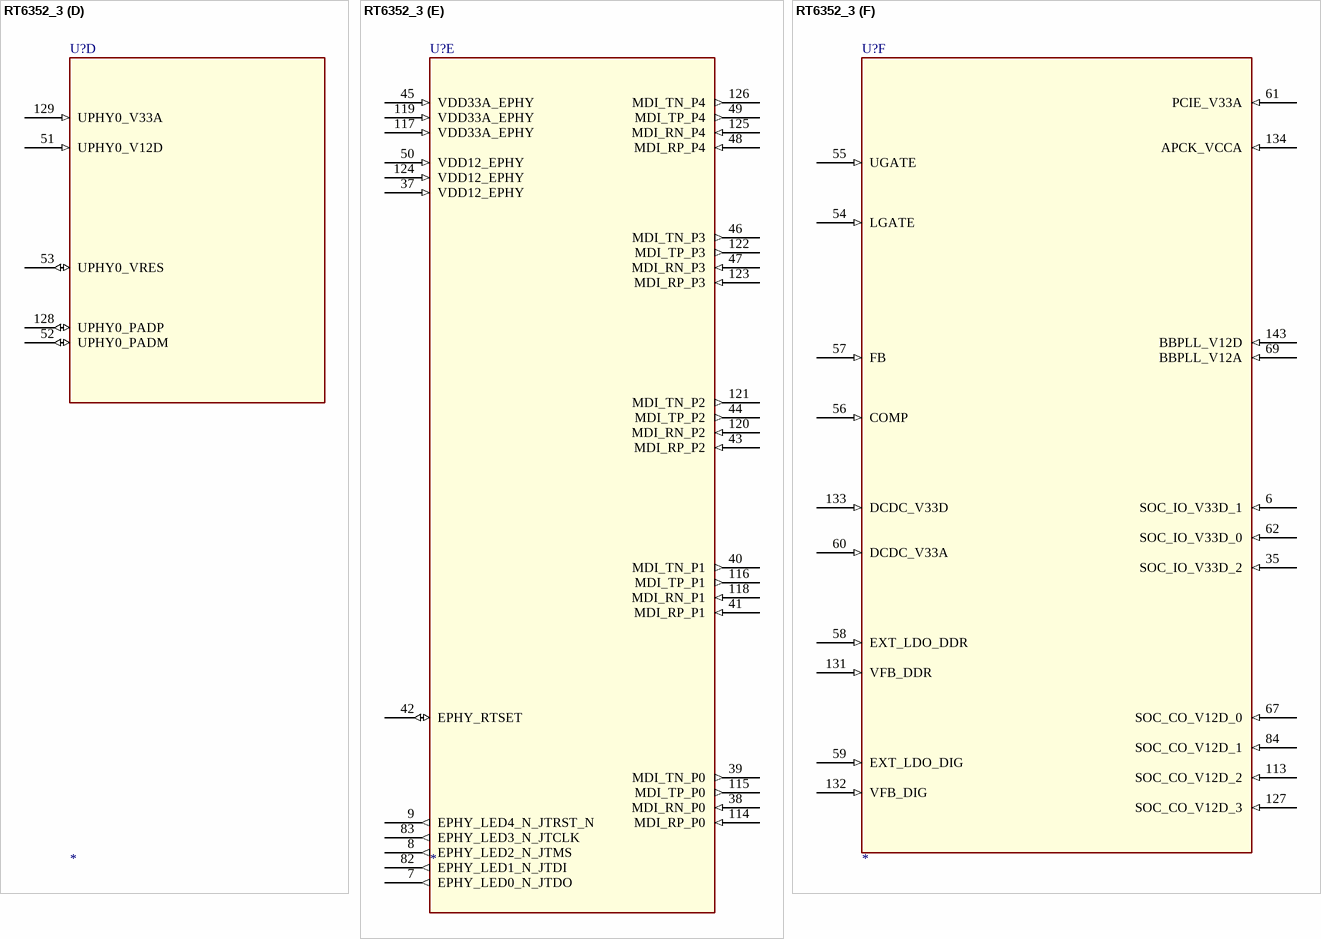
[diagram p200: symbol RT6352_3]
